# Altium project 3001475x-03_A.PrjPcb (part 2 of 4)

## Sheet 05 - JTAG, SWD, Console, UART.SchDoc: JTAG, SWD, Console, UART
size A3; PageSetup: Record=PageOptions¦CenterHorizontal=True¦CenterVertical=True¦PrintScale=0.70¦XCorrection=1.00¦YCorrection=1.00¦PrintKind=0¦BorderSize=5000000¦LeftOffset=0¦BottomOffset=0¦Orientation=2¦PaperLength=4200¦PaperWidth=2970¦Scale=100¦PaperSource=7¦PrintQuality=600¦MediaType=1¦DitherType=10¦PaperKind=A4¦PrintScaleMode=1; Author: Daniel Alesanco; SheetNumber: 5; SheetTotal: 13
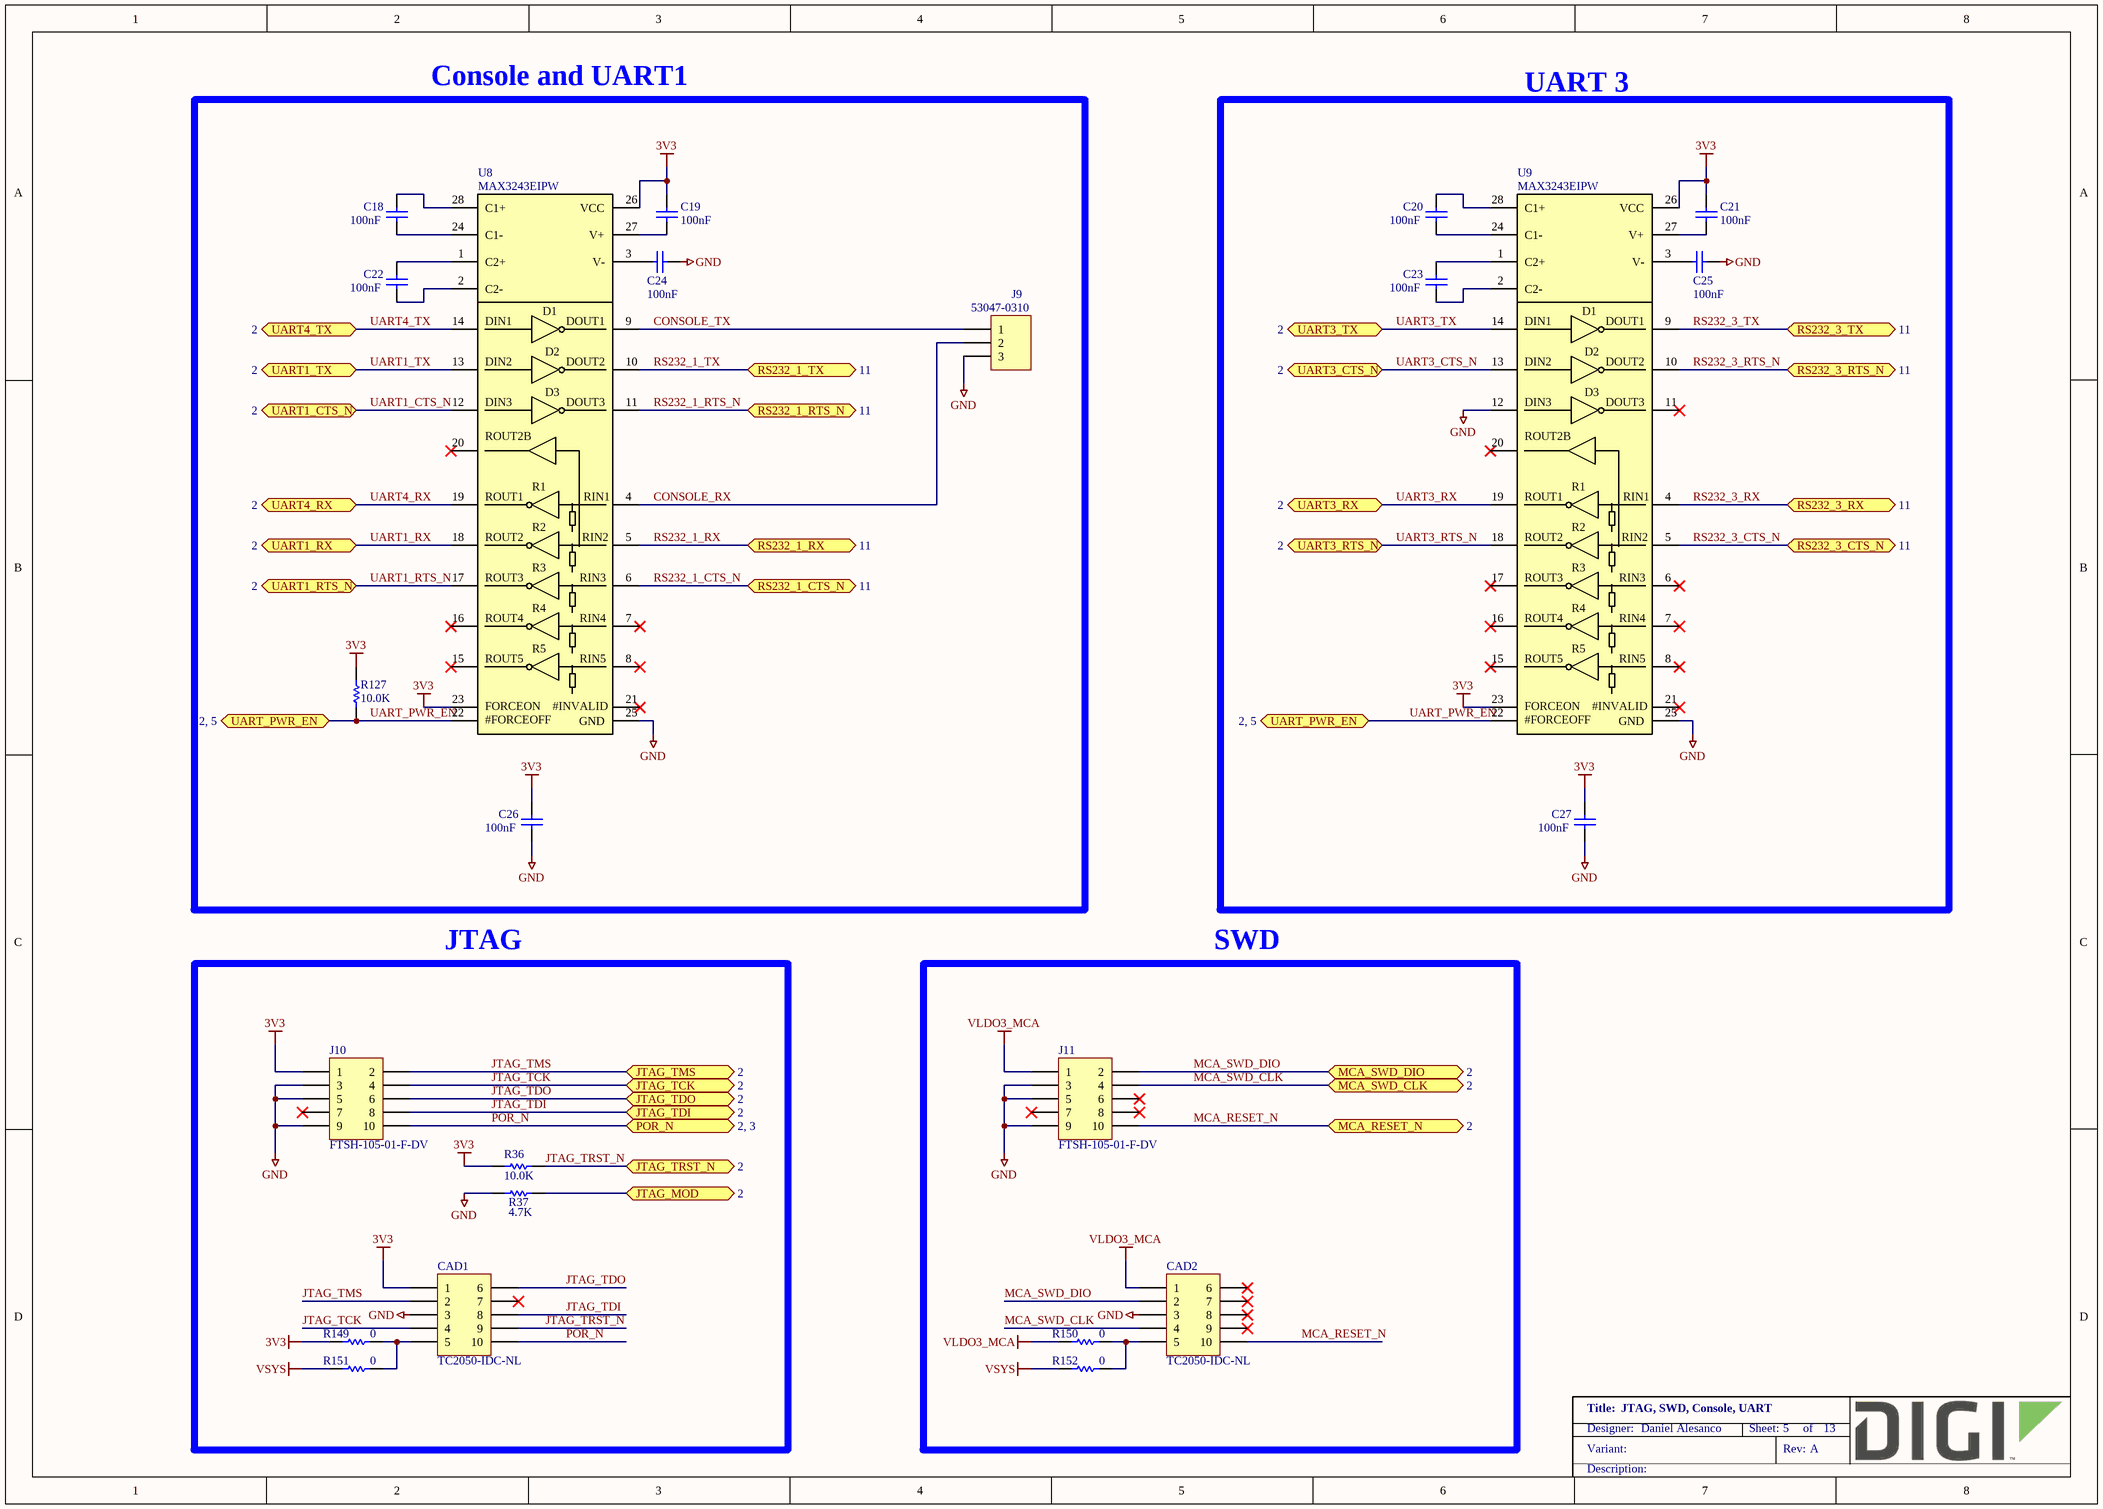
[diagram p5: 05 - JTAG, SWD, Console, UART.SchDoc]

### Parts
C18  100nF  [CAPC1005X55N]
C19  100nF  [CAPC1005X55N]
C20  100nF  [CAPC1005X55N]
C21  100nF  [CAPC1005X55N]
C22  100nF  [CAPC1005X55N]
C23  100nF  [CAPC1005X55N]
C24  100nF  [CAPC1005X55N]
C25  100nF  [CAPC1005X55N]
C26  100nF  [CAPC1005X55N]
C27  100nF  [CAPC1005X55N]
CAD1  TC2050-IDC-NL  [TC_TC2050-IDC-NL]  (no BOM)
CAD2  TC2050-IDC-NL  [TC_TC2050-IDC-NL]  (no BOM)
J9  Manufacturer_Part_Number: 53047-0310  [MOLEX_53047-0310]  (hidden comment: 1x3P)
J10  FTSH-105-01-F-DV  [SAMTEC_FTSH-105-01-F-DV]
J11  FTSH-105-01-F-DV  [SAMTEC_FTSH-105-01-F-DV]
R36  10.0K  [RESC1005X40N]
R37  4.7K  [RESC1005X40N]
R127  10.0K  [RESC1005X40N]
R149  0  [RESC1005X40N]
R150  0  [RESC1005X40N]
R151  0  [RESC1005X40N]
R152  0  [RESC1005X40N]
U8  MAX3243EIPW  [SOP65P640X120-28N]
U9  MAX3243EIPW  [SOP65P640X120-28N]

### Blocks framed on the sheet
Console and UART1: C18 C19 C22 C24 C26 J9 R127 U8
UART 3: C20 C21 C23 C25 C27 U9
JTAG: CAD1 J10 R36 R37 R149 R151
SWD: CAD2 J11 R150 R152

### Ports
JTAG_MOD (bidir, see 2), JTAG_TCK (bidir, see 2), JTAG_TDI (bidir, see 2), JTAG_TDO (bidir, see 2), JTAG_TMS (bidir, see 2), JTAG_TRST_N (bidir, see 2), MCA_RESET_N (bidir, see 2), MCA_SWD_CLK (bidir, see 2), MCA_SWD_DIO (bidir, see 2), POR_N (bidir, see 2, 3), RS232_1_CTS_N (bidir, see 11), RS232_1_RTS_N (bidir, see 11), RS232_1_RX (bidir, see 11), RS232_1_TX (bidir, see 11), RS232_3_CTS_N (bidir, see 11), RS232_3_RTS_N (bidir, see 11), RS232_3_RX (bidir, see 11), RS232_3_TX (bidir, see 11), UART1_CTS_N (bidir, see 2), UART1_RTS_N (bidir, see 2), UART1_RX (bidir, see 2), UART1_TX (bidir, see 2), UART3_CTS_N (bidir, see 2), UART3_RTS_N (bidir, see 2), UART3_RX (bidir, see 2), UART3_TX (bidir, see 2), UART4_RX (bidir, see 2), UART4_TX (bidir, see 2), UART_PWR_EN (bidir, see 2, 5)

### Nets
3V3: C19.2 C21.2 C26.2 C27.2 CAD1.1 J10.1 R36.2 R127.1 R149.1 U8.23(FORCEON) U8.26(VCC) U9.23(FORCEON) U9.26(VCC)
GND: C24.1 C25.1 C26.1 C27.1 CAD1.3 CAD2.3 J9.3 J10.3 J10.5 J10.9 J11.3 J11.5 J11.9 R37.1 U8.25(GND) U9.12(DIN3) U9.25(GND)
VLDO3_MCA: CAD2.1 J11.1 R150.1
VSYS: R151.1 R152.1
CONSOLE_RX: J9.2 U8.4(RIN1)
CONSOLE_TX: J9.1 U8.9(DOUT1)
JTAG_MOD: R37.2 ; port JTAG_MOD
JTAG_TCK: CAD1.4 J10.4 ; port JTAG_TCK
JTAG_TDI: CAD1.8 J10.8 ; port JTAG_TDI
JTAG_TDO: CAD1.6 J10.6 ; port JTAG_TDO
JTAG_TMS: CAD1.2 J10.2 ; port JTAG_TMS
JTAG_TRST_N: CAD1.9 R36.1 ; port JTAG_TRST_N
MCA_RESET_N: CAD2.10 J11.10 ; port MCA_RESET_N
MCA_SWD_CLK: CAD2.4 J11.4 ; port MCA_SWD_CLK
MCA_SWD_DIO: CAD2.2 J11.2 ; port MCA_SWD_DIO
POR_N: CAD1.10 J10.10 ; port POR_N
RS232_1_CTS_N: U8.6(RIN3) ; port RS232_1_CTS_N
RS232_1_RTS_N: U8.11(DOUT3) ; port RS232_1_RTS_N
RS232_1_RX: U8.5(RIN2) ; port RS232_1_RX
RS232_1_TX: U8.10(DOUT2) ; port RS232_1_TX
RS232_3_CTS_N: U9.5(RIN2) ; port RS232_3_CTS_N
RS232_3_RTS_N: U9.10(DOUT2) ; port RS232_3_RTS_N
RS232_3_RX: U9.4(RIN1) ; port RS232_3_RX
RS232_3_TX: U9.9(DOUT1) ; port RS232_3_TX
UART1_CTS_N: U8.12(DIN3) ; port UART1_CTS_N
UART1_RTS_N: U8.17(ROUT3) ; port UART1_RTS_N
UART1_RX: U8.18(ROUT2) ; port UART1_RX
UART1_TX: U8.13(DIN2) ; port UART1_TX
UART3_CTS_N: U9.13(DIN2) ; port UART3_CTS_N
UART3_RTS_N: U9.18(ROUT2) ; port UART3_RTS_N
UART3_RX: U9.19(ROUT1) ; port UART3_RX
UART3_TX: U9.14(DIN1) ; port UART3_TX
UART4_RX: U8.19(ROUT1) ; port UART4_RX
UART4_TX: U8.14(DIN1) ; port UART4_TX
UART_PWR_EN: R127.2 U8.22(#FORCEOFF) U9.22(#FORCEOFF) ; port UART_PWR_EN
NetC18_1: C18.1 U8.24(C1-)
NetC18_2: C18.2 U8.28(C1+)
NetC19_1: C19.1 U8.27(V+)
NetC20_1: C20.1 U9.24(C1-)
NetC20_2: C20.2 U9.28(C1+)
NetC21_1: C21.1 U9.27(V+)
NetC22_1: C22.1 U8.2(C2-)
NetC22_2: C22.2 U8.1(C2+)
NetC23_1: C23.1 U9.2(C2-)
NetC23_2: C23.2 U9.1(C2+)
NetC24_2: C24.2 U8.3(V-)
NetC25_2: C25.2 U9.3(V-)
NetCAD1_5: CAD1.5 R149.2 R151.2
NetCAD2_5: CAD2.5 R150.2 R152.2

Not connected (* = marked no-connect by the designer): CAD1 7*; CAD2 6* 7* 8* 9*; J10 7*; J11 6* 7* 8*; U8 7(RI4N)* 8(RIN5)* 15(ROUT5)* 16(ROUT4)* 20(#R2OUT)* 21(#INVALID)*; U9 6(RIN3)* 7(RI4N)* 8(RIN5)* 11(DOUT3)* 15(ROUT5)* 16(ROUT4)* 17(ROUT3)* 20(#R2OUT)* 21(#INVALID)*

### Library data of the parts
C18-C27 = 1000006: CAP 100nF 16V 10% X7R 0402; Part_Type: Capacitor; Manufacturer: Murata; Manufacturer_Part_Number: GRM155R71C104KA88D; Component_Life_Cycle_State: CAD Reviewed; Area: 0.95; Project: KITT; Tolerance: 10; Digi_PN: 14050552
CAD1 CAD2 = CAD0066: CBL PLUG-OF-NAILS 10-PIN; Part_Type: Test Point; Component_Life_Cycle_State: Created; Area: 8; Project: CCWMX6_SBC board
J9 = 1001183: CONN HEADER 3POS 1.25MM VERT TIN; Part_Type: Connector; Manufacturer: Molex; Digi_PN: 18050349; Component_Life_Cycle_State: Reviewed; Area: 17.6; Project: CCWMX6_SBC board
J10 J11 = 1000034: CONN HEADER 10POS DUAL .05" SMD; Part_Type: Connector; Manufacturer: Samtec; Note: 18000715 = Digi No. for GE WDNU; Digi_PN: 18000539; Component_Life_Cycle_State: Proven; Area: 43.55; Project: Adjustable Foundation
R36 R127 = 1000537: RES 10.0K OHM 1/10W 1% 0402 SMD; Part_Type: Resistor; Manufacturer: Panasonic - ECG; Manufacturer_Part_Number: ERJ-2RKF1002X; Component_Life_Cycle_State: CAD Reviewed; Area: 0.95; Project: KITT; Power_WV_SRF: 100; Digi_PN: 13051084
R37 = 1000038: RES 4.7K OHM 1/10W 5% 0402 SMD; Part_Type: Resistor; Manufacturer: Panasonic - ECG; Manufacturer_Part_Number: ERJ-2GEJ472X; Component_Life_Cycle_State: Proven; Area: 0.95; Project: Adjustable Foundation; Power_WV_SRF: 100; Tolerance: 5; Digi_PN: 13050549
R149-R152 = 1000076: RES 0.0 OHM 1/10W 0402 SMD; Part_Type: Resistor; Manufacturer: Panasonic - ECG; Manufacturer_Part_Number: ERJ-2GE0R00X; Component_Life_Cycle_State: Proven; Area: 0.95; Project: Adjustable Foundation; Power_WV_SRF: 10; Digi_PN: 13050387
U8 U9 = 1001499: IC RS232 3V-5.5V DRVR 28-TSSOP; Manufacturer: Texas Instruments; Digi_PN: 16050972; Component_Life_Cycle_State: Reviewed; Area: 67; Project: CCWMX6_SBC board

## Sheet 06 - Gigabit Ethernet.SchDoc: Gigabit Ethernet
size A3; PageSetup: Record=PageOptions¦CenterHorizontal=True¦CenterVertical=True¦PrintScale=0.70¦XCorrection=1.00¦YCorrection=1.00¦PrintKind=0¦BorderSize=5000000¦LeftOffset=0¦BottomOffset=0¦Orientation=2¦PaperLength=4200¦PaperWidth=2970¦Scale=100¦PaperSource=7¦PrintQuality=600¦MediaType=1¦DitherType=10¦PaperKind=A4¦PrintScaleMode=1; Author: Daniel Alesanco; SheetNumber: 6; SheetTotal: 13
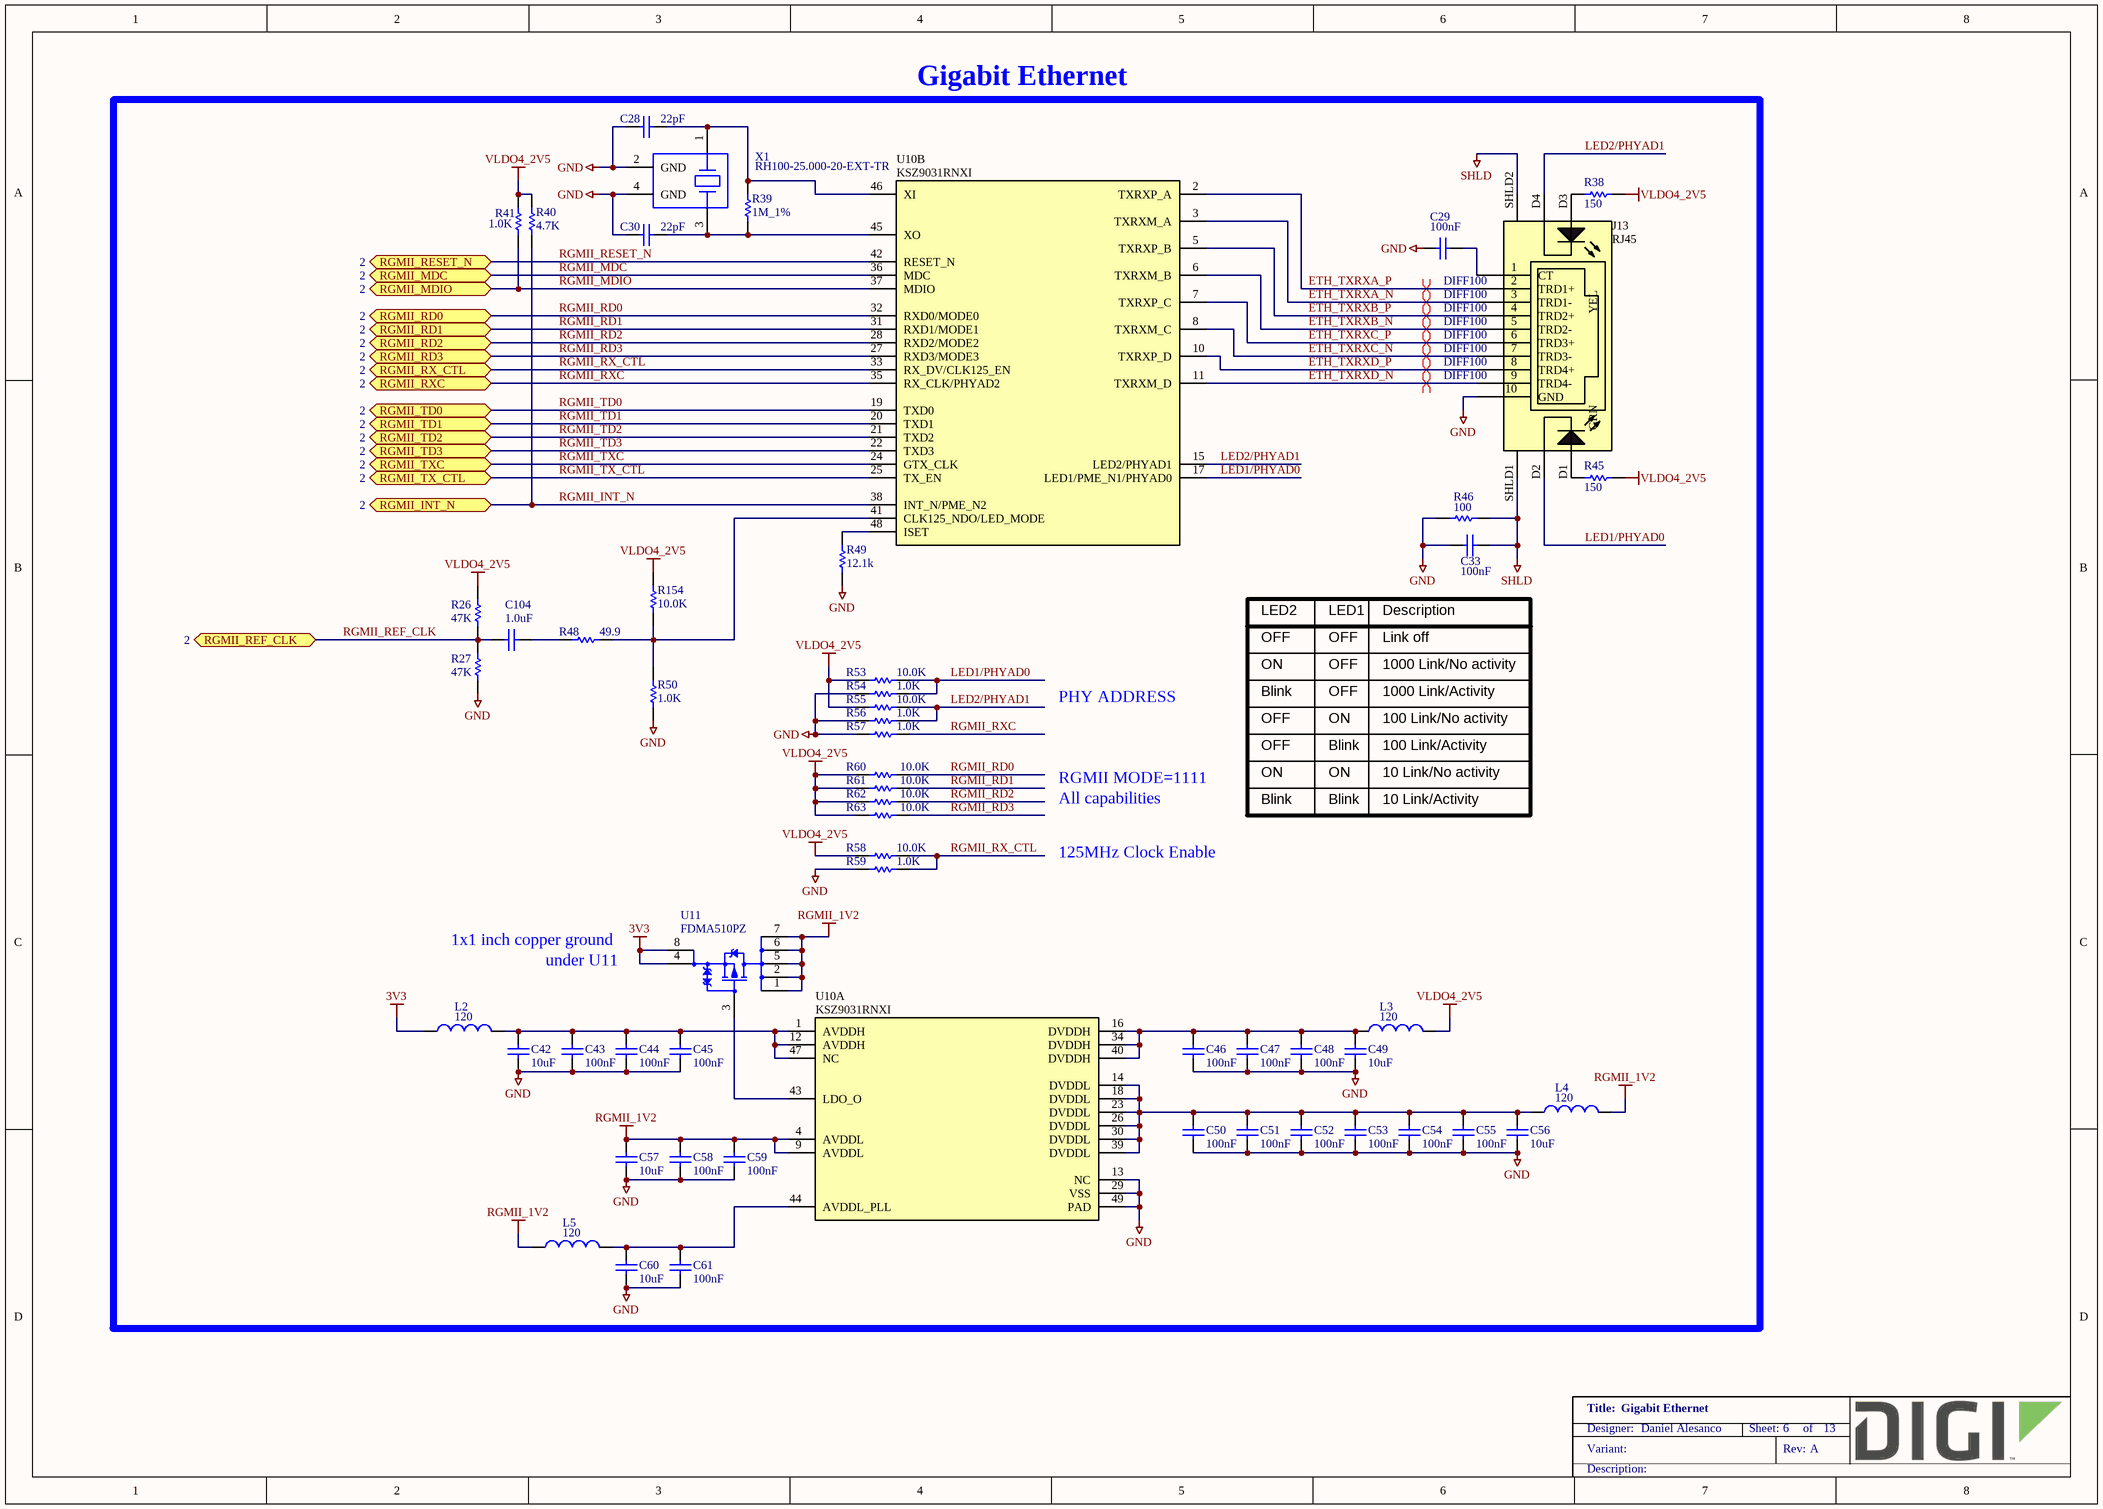
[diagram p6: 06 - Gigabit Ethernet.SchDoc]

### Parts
C28  22pF  [CAPC1005X55N]
C29  100nF  [CAPC1005X55N]
C30  22pF  [CAPC1005X55N]
C33  100nF  [CAPC1005X55N]
C42  10uF  [CAPC1005X55N]
C43  100nF  [CAPC1005X55N]
C44  100nF  [CAPC1005X55N]
C45  100nF  [CAPC1005X55N]
C46  100nF  [CAPC1005X55N]
C47  100nF  [CAPC1005X55N]
C48  100nF  [CAPC1005X55N]
C49  10uF  [CAPC1005X55N]
C50  100nF  [CAPC1005X55N]
C51  100nF  [CAPC1005X55N]
C52  100nF  [CAPC1005X55N]
C53  100nF  [CAPC1005X55N]
C54  100nF  [CAPC1005X55N]
C55  100nF  [CAPC1005X55N]
C56  10uF  [CAPC1005X55N]
C57  10uF  [CAPC1005X55N]
C58  100nF  [CAPC1005X55N]
C59  100nF  [CAPC1005X55N]
C60  10uF  [CAPC1005X55N]
C61  100nF  [CAPC1005X55N]
C104  1.0uF  [CAPC1005X55N]
J13  RJ45  [BELFUSE_61001-F]
L2  120  [INDC1005X60N]
L3  120  [INDC1005X60N]
L4  120  [INDC1005X60N]
L5  120  [INDC1005X60N]
R26  47K  [RESC1005X40N]
R27  47K  [RESC1005X40N]
R38  150  [RESC1005X40N]
R39  1M_1%  [RESC1005X40N]
R40  4.7K  [RESC1005X40N]
R41  1.0K  [RESC1005X40N]
R45  150  [RESC1005X40N]
R46  100  [RESC1005X40N]
R48  49.9  [RESC1005X40N]
R49  12.1k  [RESC1005X40N]
R50  1.0K  [RESC1005X40N]
R53  10.0K  [RESC1005X40N]
R54  1.0K  [RESC1005X40N]
R55  10.0K  [RESC1005X40N]
R56  1.0K  [RESC1005X40N]
R57  1.0K  [RESC1005X40N]
R58  10.0K  [RESC1005X40N]
R59  1.0K  [RESC1005X40N]
R60  10.0K  [RESC1005X40N]
R61  10.0K  [RESC1005X40N]
R62  10.0K  [RESC1005X40N]
R63  10.0K  [RESC1005X40N]
R154  10.0K  [RESC1005X40N]
U10  KSZ9031RNXI  [QFN50P700X700X100-49N]  (parts A,B of 2)
U11  FDMA510PZ  [DFN200X200X80-6N]
X1  RH100-25.000-20-EXT-TR  [OSC210P320X250X90-4N]

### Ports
RGMII_INT_N (bidir, see 2), RGMII_MDC (bidir, see 2), RGMII_MDIO (bidir, see 2), RGMII_RD0 (bidir, see 2), RGMII_RD1 (bidir, see 2), RGMII_RD2 (bidir, see 2), RGMII_RD3 (bidir, see 2), RGMII_REF_CLK (bidir, see 2), RGMII_RESET_N (bidir, see 2), RGMII_RX_CTL (bidir, see 2), RGMII_RXC (bidir, see 2), RGMII_TD0 (bidir, see 2), RGMII_TD1 (bidir, see 2), RGMII_TD2 (bidir, see 2), RGMII_TD3 (bidir, see 2), RGMII_TX_CTL (bidir, see 2), RGMII_TXC (bidir, see 2)

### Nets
3V3: L2.1 U11.4(S) U11.8(S)
GND: C28.1 C29.1 C30.1 C33.2 C42.1 C43.1 C44.1 C45.1 C46.1 C47.1 C48.1 C49.1 C50.1 C51.1 C52.1 C53.1 C54.1 C55.1 C56.1 C57.1 C58.1 C59.1 C60.1 C61.1 J13.10(GND) R27.1 R46.1 R49.1 R50.1 R54.2 R56.2 R57.2 R59.2 U10.13(NC) U10.29(VSS) U10.49(PAD) X1.2(GND) X1.4(GND)
RGMII_1V2: C57.2 C58.2 C59.2 L4.2 L5.1 U10.4(AVDDL) U10.9(AVDDL) U11.1(D) U11.2(D) U11.5(D) U11.6(D) U11.7(D)
SHLD: C33.1 J13.SHLD1(SHLD) J13.SHLD2(SHLD) R46.2
VLDO4_2V5: L3.2 R26.2 R38.2 R40.2 R41.2 R45.2 R53.2 R55.2 R58.2 R60.2 R61.2 R62.2 R63.2 R154.1
ETH_TXRXA_N: J13.3(TRD1-) U10.3(TXRXM_A)
ETH_TXRXA_P: J13.2(TRD1+) U10.2(TXRXP_A)
ETH_TXRXB_N: J13.5(TRD2-) U10.6(TXRXM_B)
ETH_TXRXB_P: J13.4(TRD2+) U10.5(TXRXP_B)
ETH_TXRXC_N: J13.7(TRD3-) U10.8(TXRXM_C)
ETH_TXRXC_P: J13.6(TRD3+) U10.7(TXRXP_C)
ETH_TXRXD_N: J13.9(TRD4-) U10.11(TXRXM_D)
ETH_TXRXD_P: J13.8(TRD4+) U10.10(TXRXP_D)
LED1/PHYAD0: J13.D2 R53.1 R54.1 U10.17(LED1/PME_N1/PHYAD0)
LED2/PHYAD1: J13.D4 R55.1 R56.1 U10.15(LED2/PHYAD1)
RGMII_INT_N: R40.1 U10.38(INT_N/PME_N2) ; port RGMII_INT_N
RGMII_MDC: U10.36(MDC) ; port RGMII_MDC
RGMII_MDIO: R41.1 U10.37(MDIO) ; port RGMII_MDIO
RGMII_RD0: R60.1 U10.32(RXD0/MODE0) ; port RGMII_RD0
RGMII_RD1: R61.1 U10.31(RXD1/MODE1) ; port RGMII_RD1
RGMII_RD2: R62.1 U10.28(RXD2/MODE2) ; port RGMII_RD2
RGMII_RD3: R63.1 U10.27(RXD3/MODE3) ; port RGMII_RD3
RGMII_REF_CLK: C104.1 R26.1 R27.2 ; port RGMII_REF_CLK
RGMII_RESET_N: U10.42(RESET_N) ; port RGMII_RESET_N
RGMII_RX_CTL: R58.1 R59.1 U10.33(RX_DV/CLK125_EN) ; port RGMII_RX_CTL
RGMII_RXC: R57.1 U10.35(RX_CLK/PHYAD2) ; port RGMII_RXC
RGMII_TD0: U10.19(TXD0) ; port RGMII_TD0
RGMII_TD1: U10.20(TXD1) ; port RGMII_TD1
RGMII_TD2: U10.21(TXD2) ; port RGMII_TD2
RGMII_TD3: U10.22(TXD3) ; port RGMII_TD3
RGMII_TX_CTL: U10.25(TX_EN) ; port RGMII_TX_CTL
RGMII_TXC: U10.24(GTX_CLK) ; port RGMII_TXC
NetC28_2: C28.2 R39.2 U10.46(XI) X1.1
NetC29_2: C29.2 J13.1(CT)
NetC30_2: C30.2 R39.1 U10.45(XO) X1.3
NetC42_2: C42.2 C43.2 C44.2 C45.2 L2.2 U10.1(AVDDH) U10.12(AVDDH) U10.47(NC)
NetC46_2: C46.2 C47.2 C48.2 C49.2 L3.1 U10.16(DVDDH) U10.34(DVDDH) U10.40(DVDDH)
NetC50_2: C50.2 C51.2 C52.2 C53.2 C54.2 C55.2 C56.2 L4.1 U10.14(DVDDL) U10.18(DVDDL) U10.23(DVDDL) U10.26(DVDDL) U10.30(DVDDL) U10.39(DVDDL)
NetC60_2: C60.2 C61.2 L5.2 U10.44(AVDDL_PLL)
NetC104_2: C104.2 R48.1
NetJ13_D1: J13.D1 R45.1
NetJ13_D3: J13.D3 R38.1
NetR48_2: R48.2 R50.2 R154.2 U10.41(CLK125_NDO/LED_MODE)
NetR49_2: R49.2 U10.48(ISET)
NetU10_43: U10.43(LDO_O) U11.3(G)

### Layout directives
differential pair; net class DIFF100: ETH_TXRXA_N, ETH_TXRXA_P, ETH_TXRXB_N, ETH_TXRXB_P, ETH_TXRXC_N, ETH_TXRXC_P, ETH_TXRXD_N, ETH_TXRXD_P

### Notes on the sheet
- Gigabit Ethernet
- LED2
- OFF
- LED1
- Description
- Link off
- PHY ADDRESS
- ON
- Blink
- 1000 Link/No activity
- 1000 Link/Activity
- 100 Link/No activity
- RGMII MODE=1111
- 100 Link/Activity
- 10 Link/No activity
- All capabilities
- 125MHz Clock Enable
- 10 Link/Activity
- 1x1 inch copper ground
- under U11

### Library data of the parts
C28 C30 = 1001166: CAP CER 22PF 50V 5% NP0 0402; Part_Type: Capacitor; Manufacturer: Murata; Manufacturer_Part_Number: GRM1555C1H220JA01D; Digi_PN: 14050367; Component_Life_Cycle_State: Reviewed; Area: 0.95; Project: CCWMX6_SBC board; Temp_Coef: C0G, NP0; Note: 14050749 = Digi No. for GE WDNU
C29 C33 C43-C48 C50-C55 C58 C59 C61 = 1000006: as C18-C27 on sheet 05 - JTAG, SWD, Console, UART
C42 C49 C56 C57 C60 = 1001168: CAP CER 10UF 10V 20% X5R 0402; Part_Type: Capacitor; Manufacturer: Samsung; Manufacturer_Part_Number: CL05A106MP5NUNC; Digi_PN: 14050689; Component_Life_Cycle_State: Reviewed; Area: 0.95; Project: CCWMX6_SBC board
C104 = 1001167: CAP CER 1UF 10V 10% X5R 0402; Part_Type: Capacitor; Manufacturer: Murata; Manufacturer_Part_Number: GRM155R61A105KE15D; Digi_PN: 14050399; Component_Life_Cycle_State: Reviewed; Area: 0.95; Project: CCWMX6_SBC board
J13 = 1001966: CONN MAGJACK 1PORT 1000 BASE-T, -40/85°C; Part_Type: Connector; Manufacturer: XMultiple; Manufacturer_Part_Number: XMG-1108D1006-1; Digi_PN: 18000732; Component_Life_Cycle_State: Created; Area: 348,2467; Project: CCWMX6_SBC board
L2-L5 = 1001175: FERRITE BEAD 120 OHM .35A 0402; Part_Type: Filter; Manufacturer: Wurth Electronics Inc; Manufacturer_Part_Number: 7427927112; Digi_PN: 21000128; Component_Life_Cycle_State: Reviewed; Area: 1.12; Project: CCWMX6_SBC board
R26 R27 = 1001155: RES 47.0K OHM 1/16W 1% 0402 SMD; Part_Type: Resistor; Manufacturer: Vishay Dale; Manufacturer_Part_Number: CRCW040247K0FKED; Digi_PN: 13050646; Component_Life_Cycle_State: Reviewed; Area: 0.95; Project: CCWMX6_SBC board
R38 R45 = 1000465: RES 150 OHM 1/10W 1% 0402 SMD; Part_Type: Resistor; Manufacturer: Panasonic - ECG; Manufacturer_Part_Number: ERJ-2RKF1500X; Digi_PN: 13050557; Component_Life_Cycle_State: CAD Reviewed; Area: 0.95; Project: KITT; Power_WV_SRF: 100
R39 = 1000971: RES 1.00M OHM 1/16W 1% 0402 SMD; Part_Type: Resistor; Manufacturer: Yageo; Manufacturer_Part_Number: RC0402FR-071ML; Digi_PN: 13050561; Component_Life_Cycle_State: Reviewed; Area: 0.95; Project: ConnectCore i.MX6 module; Power_WV_SRF: 63; Tolerance: 1; Note: 13051098 = Digi No. for GE WDNU
R40 = 1000038: as R37 on sheet 05 - JTAG, SWD, Console, UART
R41 R50 R54 R56 R57 R59 = 1000079: RES 1.00K OHM 1/10W 1% 0402 SMD; Part_Type: Resistor; Manufacturer: Panasonic - ECG; Manufacturer_Part_Number: ERJ-2RKF1001X; Digi_PN: 13051085; Component_Life_Cycle_State: Proven; Area: 0.95; Project: Adjustable Foundation; Power_WV_SRF: 10
R46 = 1000467: RES 100 OHM 1/10W 1% 0402 SMD; Part_Type: Resistor; Manufacturer: Panasonic - ECG; Manufacturer_Part_Number: ERJ-2RKF1000X; Component_Life_Cycle_State: CAD Reviewed; Area: 0.95; Project: KITT; Digi_PN: 13051087
R48 = 1000466: RES 49.9 OHM 1/10W 1% 0402 SMD; Part_Type: Resistor; Manufacturer: Panasonic - ECG; Manufacturer_Part_Number: ERJ-2RKF49R9X; Component_Life_Cycle_State: CAD Reviewed; Area: 0.95; Project: KITT; Power_WV_SRF: 100; Digi_PN: 13051083
R49 = 1000828: RES 12.1K OHM 1/10W 1% 0402 SMD; Part_Type: Resistor; Manufacturer: Panasonic - ECG; Manufacturer_Part_Number: ERJ-2RKF1212X; Component_Life_Cycle_State: Reviewed; Area: 0.95; Project: SmartMeter2; Power_WV_SRF: 100; Digi_PN: 13051088
R53 R55 R58 R60-R63 R154 = 1000537: as R36 on sheet 05 - JTAG, SWD, Console, UART
U10 = 1001110: IC TXRX ETHERNET 48-QFN; Manufacturer: Micrel; Digi_PN: 16051862; Component_Life_Cycle_State: Reviewed; Area: 49; Project: CCWMX6_SBC board
U11 = 1001205: MOSFET P-CH 20V 7.8A 6-MICROFET; Part_Type: IC; Manufacturer: Fairchild Semiconductor; Digi_PN: 17050636; Component_Life_Cycle_State: Reviewed; Area: 4; Project: CCWMX6_SBC board
X1 = 1001497: SMCRY,25MHZ 50PPM 20PF RH100 EXT; Part_Type: Crystals-Oscillators; Manufacturer: Raltron; Digi_PN: 20000285; Component_Life_Cycle_State: Reviewed; Area: 3.2; Project: CCWMX6_SBC board

## Sheet 07 - USB OTG, USB HUB, USB Host.SchDoc: USB OTG, USB Hub, USB Host
size A3; PageSetup: Record=PageOptions¦CenterHorizontal=True¦CenterVertical=True¦PrintScale=0.70¦XCorrection=1.00¦YCorrection=1.00¦PrintKind=0¦BorderSize=5000000¦LeftOffset=0¦BottomOffset=0¦Orientation=2¦PaperLength=4200¦PaperWidth=2970¦Scale=100¦PaperSource=7¦PrintQuality=600¦MediaType=1¦DitherType=10¦PaperKind=A4¦PrintScaleMode=1; Author: Daniel Alesanco; SheetNumber: 7; SheetTotal: 13
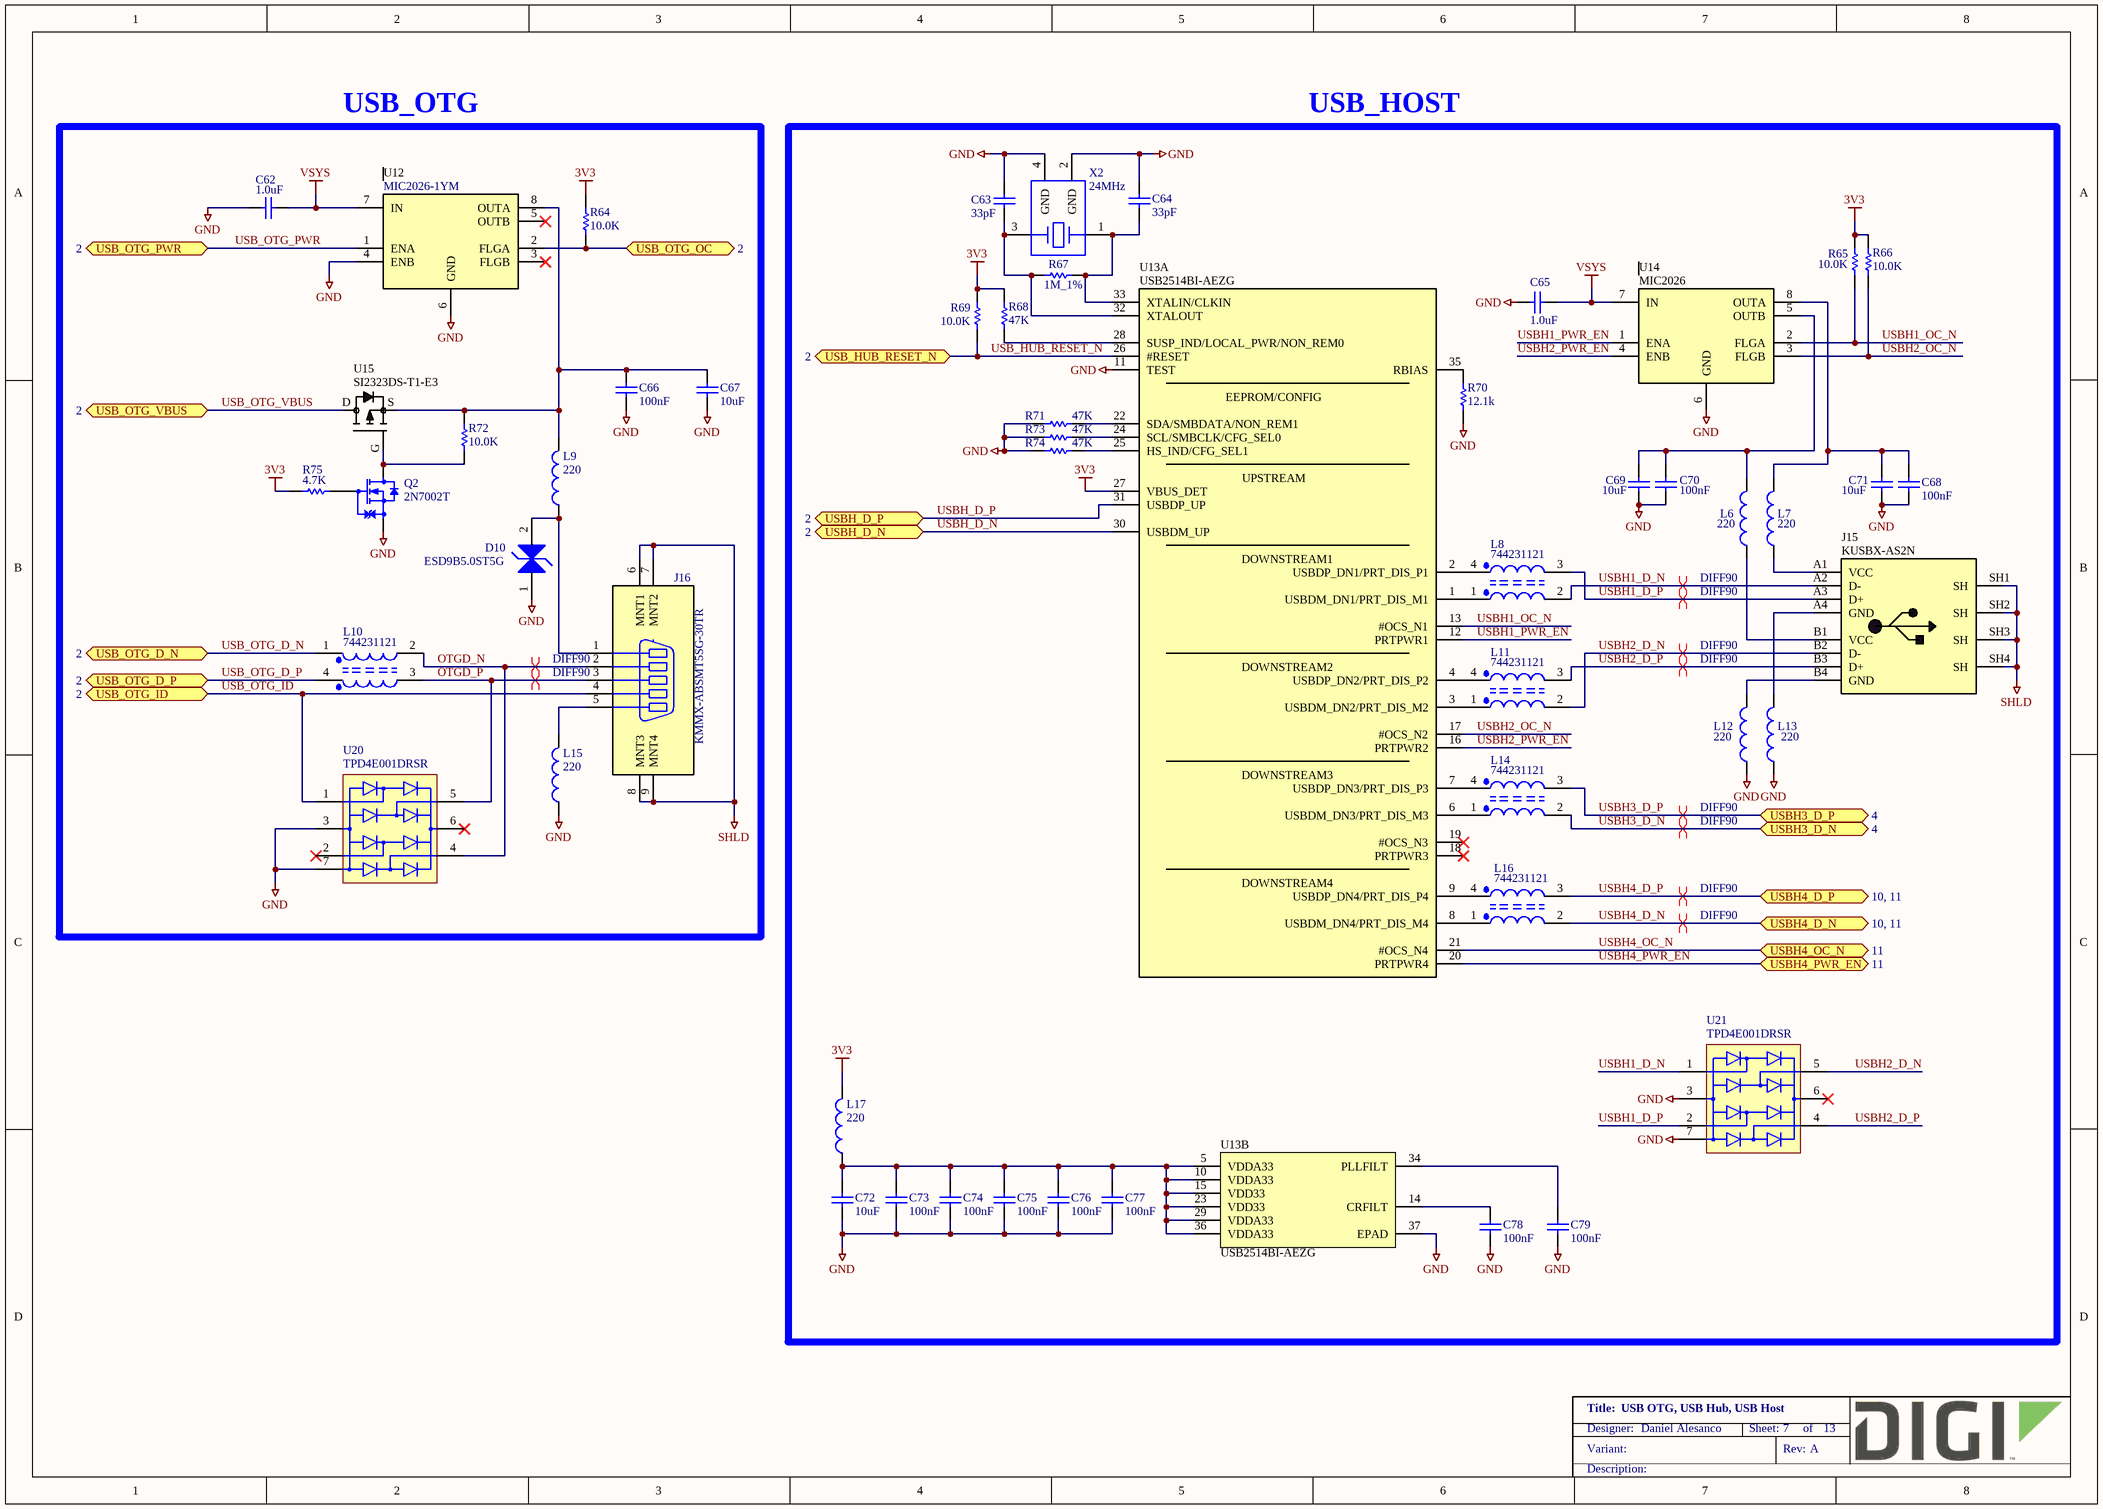
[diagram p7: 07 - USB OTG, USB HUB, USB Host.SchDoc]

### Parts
C62  1.0uF  [CAPC1005X55N]
C63  33pF  [CAPC1005X55N]
C64  33pF  [CAPC1005X55N]
C65  1.0uF  [CAPC1005X55N]
C66  100nF  [CAPC1005X55N]
C67  10uF  [CAPC1005X55N]
C68  100nF  [CAPC1005X55N]
C69  10uF  [CAPC1005X55N]
C70  100nF  [CAPC1005X55N]
C71  10uF  [CAPC1005X55N]
C72  10uF  [CAPC1005X55N]
C73  100nF  [CAPC1005X55N]
C74  100nF  [CAPC1005X55N]
C75  100nF  [CAPC1005X55N]
C76  100nF  [CAPC1005X55N]
C77  100nF  [CAPC1005X55N]
C78  100nF  [CAPC1005X55N]
C79  100nF  [CAPC1005X55N]
D10  ESD9B5.0ST5G  [SODFL1006X43N12]
J15  KUSBX-AS2N  [KYCON_KUSBX-AS2N]
J16  KMMX-ABSMT5SG-30TR  [KYCON_KMMX-ABSMT5]
L6  220  [INDC2013X110N]
L7  220  [INDC2013X110N]
L8  744231121  [FIL_DLW21H]
L9  220  [INDC2013X110N]
L10  744231121  [FIL_DLW21H]
L11  744231121  [FIL_DLW21H]
L12  220  [INDC2013X110N]
L13  220  [INDC2013X110N]
L14  744231121  [FIL_DLW21H]
L15  220  [INDC2013X110N]
L16  744231121  [FIL_DLW21H]
L17  220  [INDC2013X110N]
Q2  2N7002T  [SOTFL50P160X80_GSD-3N]
R64  10.0K  [RESC1005X40N]
R65  10.0K  [RESC1005X40N]
R66  10.0K  [RESC1005X40N]
R67  1M_1%  [RESC1005X40N]
R68  47K  [RESC1005X40N]
R69  10.0K  [RESC1005X40N]
R70  12.1k  [RESC1005X40N]
R71  47K  [RESC1005X40N]
R72  10.0K  [RESC1005X40N]
R73  47K  [RESC1005X40N]
R74  47K  [RESC1005X40N]
R75  4.7K  [RESC1005X40N]
U12  Manufacturer_Part_Number: MIC2026-1YM  [SOIC127P600X175-8N]  (hidden comment: MIC2026)
U13  USB2514BI-AEZG  [QFN50P600X600X100-37AN]  (parts A,B of 2)
U14  MIC2026  [SOIC127P600X175-8N]
U15  SI2323DS-T1-E3  [SOT95P240X110_GSD-3N]
U20  TPD4E001DRSR  [SON95P300X300X80-7N]
U21  TPD4E001DRSR  [SON95P300X300X80-7N]
X2  24MHz  [XTAL_C3E-3427]

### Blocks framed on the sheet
USB_OTG: C62 C66 C67 D10 J16 L9 L10 L15 Q2 R64 R72 R75 U12 U15 U20
USB_HOST: C63-C65 C68-C79 J15 L6-L8 L11-L14 L16 L17 R65-R71 R73 R74 U13 U14 U21 X2

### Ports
USB_HUB_RESET_N (bidir, see 2), USB_OTG_D_N (bidir, see 2), USB_OTG_D_P (bidir, see 2), USB_OTG_ID (bidir, see 2), USB_OTG_OC (bidir, see 2), USB_OTG_PWR (bidir, see 2), USB_OTG_VBUS (bidir, see 2), USBH3_D_N (bidir, see 4), USBH3_D_P (bidir, see 4), USBH4_D_N (bidir, see 10, 11), USBH4_D_P (bidir, see 10, 11), USBH4_OC_N (bidir, see 11), USBH4_PWR_EN (bidir, see 11), USBH_D_N (bidir, see 2), USBH_D_P (bidir, see 2)

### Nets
3V3: L17.2 R64.2 R65.2 R66.2 R68.2 R69.1 R75.1 U13.27(VBUS_DET)
GND: C62.1 C63.2 C64.2 C65.2 C66.1 C67.1 C68.1 C69.1 C70.1 C71.1 C72.1 C73.1 C74.1 C75.1 C76.1 C77.1 C78.1 C79.1 D10.1 L12.1 L13.1 L15.1 Q2.S R70.1 R71.1 R73.1 R74.1 U12.4(ENB) U12.6(GND) U13.11(TEST) U13.37(EPAD) U14.6(GND) U20.3(GND) U20.7(GND) U21.3(GND) U21.7(GND) X2.2(GND) X2.4(GND)
SHLD: J15.SH1(SH) J15.SH2(SH) J15.SH3(SH) J15.SH4(SH) J16.6(MNT1) J16.7(MNT2) J16.8(MNT3) J16.9(MNT4)
VSYS: C62.2 C65.1 U12.7(IN) U14.7(IN)
OTGD_N: J16.2 L10.2 U20.4(I/O)
OTGD_P: J16.3 L10.3 U20.5(I/O)
USB_HUB_RESET_N: R69.2 U13.26(#RESET) ; port USB_HUB_RESET_N
USB_OTG_D_N: L10.1 ; port USB_OTG_D_N
USB_OTG_D_P: L10.4 ; port USB_OTG_D_P
USB_OTG_ID: J16.4 U20.1(I/O) ; port USB_OTG_ID
USB_OTG_OC: R64.1 U12.2(FLGA) ; port USB_OTG_OC
USB_OTG_PWR: U12.1(ENA) ; port USB_OTG_PWR
USB_OTG_VBUS: U15.D ; port USB_OTG_VBUS
USBH1_D_N: J15.A2(D-) L8.2 U21.1(I/O)
USBH1_D_P: J15.A3(D+) L8.3 U21.2(I/O)
USBH1_OC_N: R65.1 U13.13(#OCS_N1) U14.2(FLGA)
USBH1_PWR_EN: U13.12(PRTPWR1) U14.1(ENA)
USBH2_D_N: J15.B2(D-) L11.2 U21.5(I/O)
USBH2_D_P: J15.B3(D+) L11.3 U21.4(I/O)
USBH2_OC_N: R66.1 U13.17(#OCS_N2) U14.3(FLGB)
USBH2_PWR_EN: U13.16(PRTPWR2) U14.4(ENB)
USBH3_D_N: L14.2 ; port USBH3_D_N
USBH3_D_P: L14.3 ; port USBH3_D_P
USBH4_D_N: L16.2 ; port USBH4_D_N
USBH4_D_P: L16.3 ; port USBH4_D_P
USBH4_OC_N: U13.21(#OCS_N4) ; port USBH4_OC_N
USBH4_PWR_EN: U13.20(PRTPWR4) ; port USBH4_PWR_EN
USBH_D_N: U13.30(USBDM_UP) ; port USBH_D_N
USBH_D_P: U13.31(USBDP_UP) ; port USBH_D_P
NetC63_1: C63.1 R67.1 U13.32(XTALOUT) X2.3
NetC64_1: C64.1 R67.2 U13.33(XTALIN/CLKIN) X2.1
NetC66_2: C66.2 C67.2 L9.2 R72.1 U12.8(OUTA) U15.S
NetC68_2: C68.2 C71.2 L7.2 U14.8(OUTA)
NetC69_2: C69.2 C70.2 L6.2 U14.5(OUTB)
NetC72_2: C72.2 C73.2 C74.2 C75.2 C76.2 C77.2 L17.1 U13.5(VDDA33) U13.10(VDDA33) U13.15(VDD33) U13.23(VDD33) U13.29(VDDA33) U13.36(VDDA33)
NetC78_2: C78.2 U13.14(CRFILT)
NetC79_2: C79.2 U13.34(PLLFILT)
NetD10_2: D10.2 J16.1 L9.1
NetJ15_A1: J15.A1(VCC) L7.1
NetJ15_A4: J15.A4(GND) L13.2
NetJ15_B1: J15.B1(VCC) L6.1
NetJ15_B4: J15.B4(GND) L12.2
NetJ16_5: J16.5 L15.2
NetL8_1: L8.1 U13.1(USBDM_DN1/PRT_DIS_M1)
NetL8_4: L8.4 U13.2(USBDP_DN1/PRT_DIS_P1)
NetL11_1: L11.1 U13.3(USBDM_DN2/PRT_DIS_M2)
NetL11_4: L11.4 U13.4(USBDP_DN2/PRT_DIS_P2)
NetL14_1: L14.1 U13.6(USBDM_DN3/PRT_DIS_M3)
NetL14_4: L14.4 U13.7(USBDP_DN3/PRT_DIS_P3)
NetL16_1: L16.1 U13.8(USBDM_DN4/PRT_DIS_M4)
NetL16_4: L16.4 U13.9(USBDP_DN4/PRT_DIS_P4)
NetQ2_D: Q2.D R72.2 U15.G
NetQ2_G: Q2.G R75.2
NetR68_1: R68.1 U13.28(SUSP_IND/LOCAL_PWR/NON_REM0)
NetR70_2: R70.2 U13.35(RBIAS)
NetR71_2: R71.2 U13.22(SDA/SMBDATA/NON_REM1)
NetR73_2: R73.2 U13.24(SCL/SMBCLK/CFG_SEL0)
NetR74_2: R74.2 U13.25(HS_IND/CFG_SEL1)

Not connected (* = marked no-connect by the designer): U12 3(FLGB)* 5(OUTB)*; U13 18(PRTPWR3)* 19(#OCS_N3)*; U20 2(I/O)* 6(VCC)*; U21 6(VCC)*

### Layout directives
differential pair; net class DIFF90: OTGD_N, OTGD_P, USBH1_D_N, USBH1_D_P, USBH2_D_N, USBH2_D_P, USBH3_D_N, USBH3_D_P, USBH4_D_N, USBH4_D_P

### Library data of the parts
C62 C65 = 1001167: as C104 on sheet 06 - Gigabit Ethernet
C63 C64 = 1002646: CAP CER 33PF 50V C0G/NP0 0402; Part_Type: Capacitor; Manufacturer: Murata; Manufacturer_Part_Number: GCM1555C1H330JA16D; Digi_PN: 14050400; Component_Life_Cycle_State: Reviewed; Area: 2.12; Project: SmartSense - International Certification; Voltage: 50; Tolerance: 5%
C66 C68 C70 C73-C79 = 1000006: as C18-C27 on sheet 05 - JTAG, SWD, Console, UART
C67 C69 C71 C72 = 1001168: as C42 on sheet 06 - Gigabit Ethernet
D10 = 1001264: TVS DIODE 5VWM SOD923; Part_Type: Diodes; Manufacturer: On Semiconductor; Digi_PN: 17050587; Component_Life_Cycle_State: Reviewed; Area: 1.5; Project: CCWMX6_SBC board
J15 = 1001121: USB Stacked Dual A type; Part_Type: Connector; Manufacturer: KYCON; Digi_PN: 18000276; Component_Life_Cycle_State: Reviewed; Area: 164; Project: CCWMX6_SBC board
J16 = 1001117: CONN RECEPT MICRO-USB TYPE AB R/A; Part_Type: Connector; Manufacturer: KYCON; Digi_PN: 18000401; Component_Life_Cycle_State: Reviewed; Area: 40; Project: CCWMX6_SBC board
L6 L7 L9 L12 L13 L15 L17 = 1001174: FERRITE BEAD 220 OHM 2.0A 0805; Manufacturer: Wurth Electronics Inc; Manufacturer_Part_Number: 742792022; Digi_PN: 21000146; Component_Life_Cycle_State: Reviewed; Area: 4.24; Project: CCWMX6_SBC board
L8 L10 L11 L14 L16 = 1001173: CHOKE COM MODE 120 OHM .37A; Part_Type: Inductor; Manufacturer: Wurth Electronics Inc; Digi_PN: 21000143; Component_Life_Cycle_State: Reviewed; Area: 2.4; Project: CCWMX6_SBC board
Q2 = 1000715: MOSFET N-CH 60V 115MA SOT-523F; Part_Type: Transistor; Manufacturer: Fairchild Semiconductor; Digi_PN: 17050797; Component_Life_Cycle_State: CAD Reviewed; Area: 3.06; Project: SmartMeter2; Note: 17050841 = Digi No. for GE WDNU
R64-R66 R69 R72 = 1000537: as R36 on sheet 05 - JTAG, SWD, Console, UART
R67 = 1000971: as R39 on sheet 06 - Gigabit Ethernet
R68 R71 R73 R74 = 1001155: as R26 on sheet 06 - Gigabit Ethernet
R70 = 1000828: as R49 on sheet 06 - Gigabit Ethernet
R75 = 1000038: as R37 on sheet 05 - JTAG, SWD, Console, UART
U12 = 1001143: IC SW DISTRIBUTION 2CHAN 8SOIC; Manufacturer: Micrel; Digi_PN: 16051879; Component_Life_Cycle_State: Reviewed; Area: 29.58; Project: CCWMX6_SBC board
U13 = 1001114: 4-PORT USB 2.0 HUB CTRLR 36VQFN; Part_Type: IC; Manufacturer: SMSC; Digi_PN: 16051280; Component_Life_Cycle_State: Reviewed; Area: 36; Project: CCWMX6_SBC board
U14 = 1001143: IC SW DISTRIBUTION 2CHAN 8SOIC; Manufacturer: Micrel; Manufacturer_Part_Number: MIC2026-1YM; Digi_PN: 16051879; Component_Life_Cycle_State: Reviewed; Area: 29.58; Project: CCWMX6_SBC board
U15 = 1001163: MOSFET P-CH 20V 3.7A SOT23-3; Part_Type: IC; Manufacturer: Vishay Siliconix; Digi_PN: 17050358; Component_Life_Cycle_State: Reviewed; Area: 10.92; Project: CCWMX6_SBC board
U20 U21 = 1001265: TVS DIODE 5.5VWM 6SON; Part_Type: IC; Manufacturer: Texas Instruments; Digi_PN: 17050690; Component_Life_Cycle_State: Reviewed; Area: 10; Project: CCWMX6_SBC board; Note: 17050839 = Digi No. for GE WDNU
X2 = 1001134: CRYSTAL 24MHZ 18PF SMD; Part_Type: Crystals-Oscillators; Manufacturer: Aker; Manufacturer_Part_Number: C3E-24.000-18-3030-X-R; Digi_PN: 20000223; Component_Life_Cycle_State: Reviewed; Area: 9.18; Project: CCWMX6_SBC board

## Sheet 08 - Displays, HDMI, Cameras.SchDoc: Displays, HDMI and Cameras
size A3; PageSetup: Record=PageOptions¦CenterHorizontal=True¦CenterVertical=True¦PrintScale=0.70¦XCorrection=1.00¦YCorrection=1.00¦PrintKind=0¦BorderSize=5000000¦LeftOffset=0¦BottomOffset=0¦Orientation=2¦PaperLength=4200¦PaperWidth=2970¦Scale=100¦PaperSource=7¦PrintQuality=600¦MediaType=1¦DitherType=10¦PaperKind=A4¦PrintScaleMode=1; Author: Daniel Alesanco; SheetNumber: 8; SheetTotal: 13
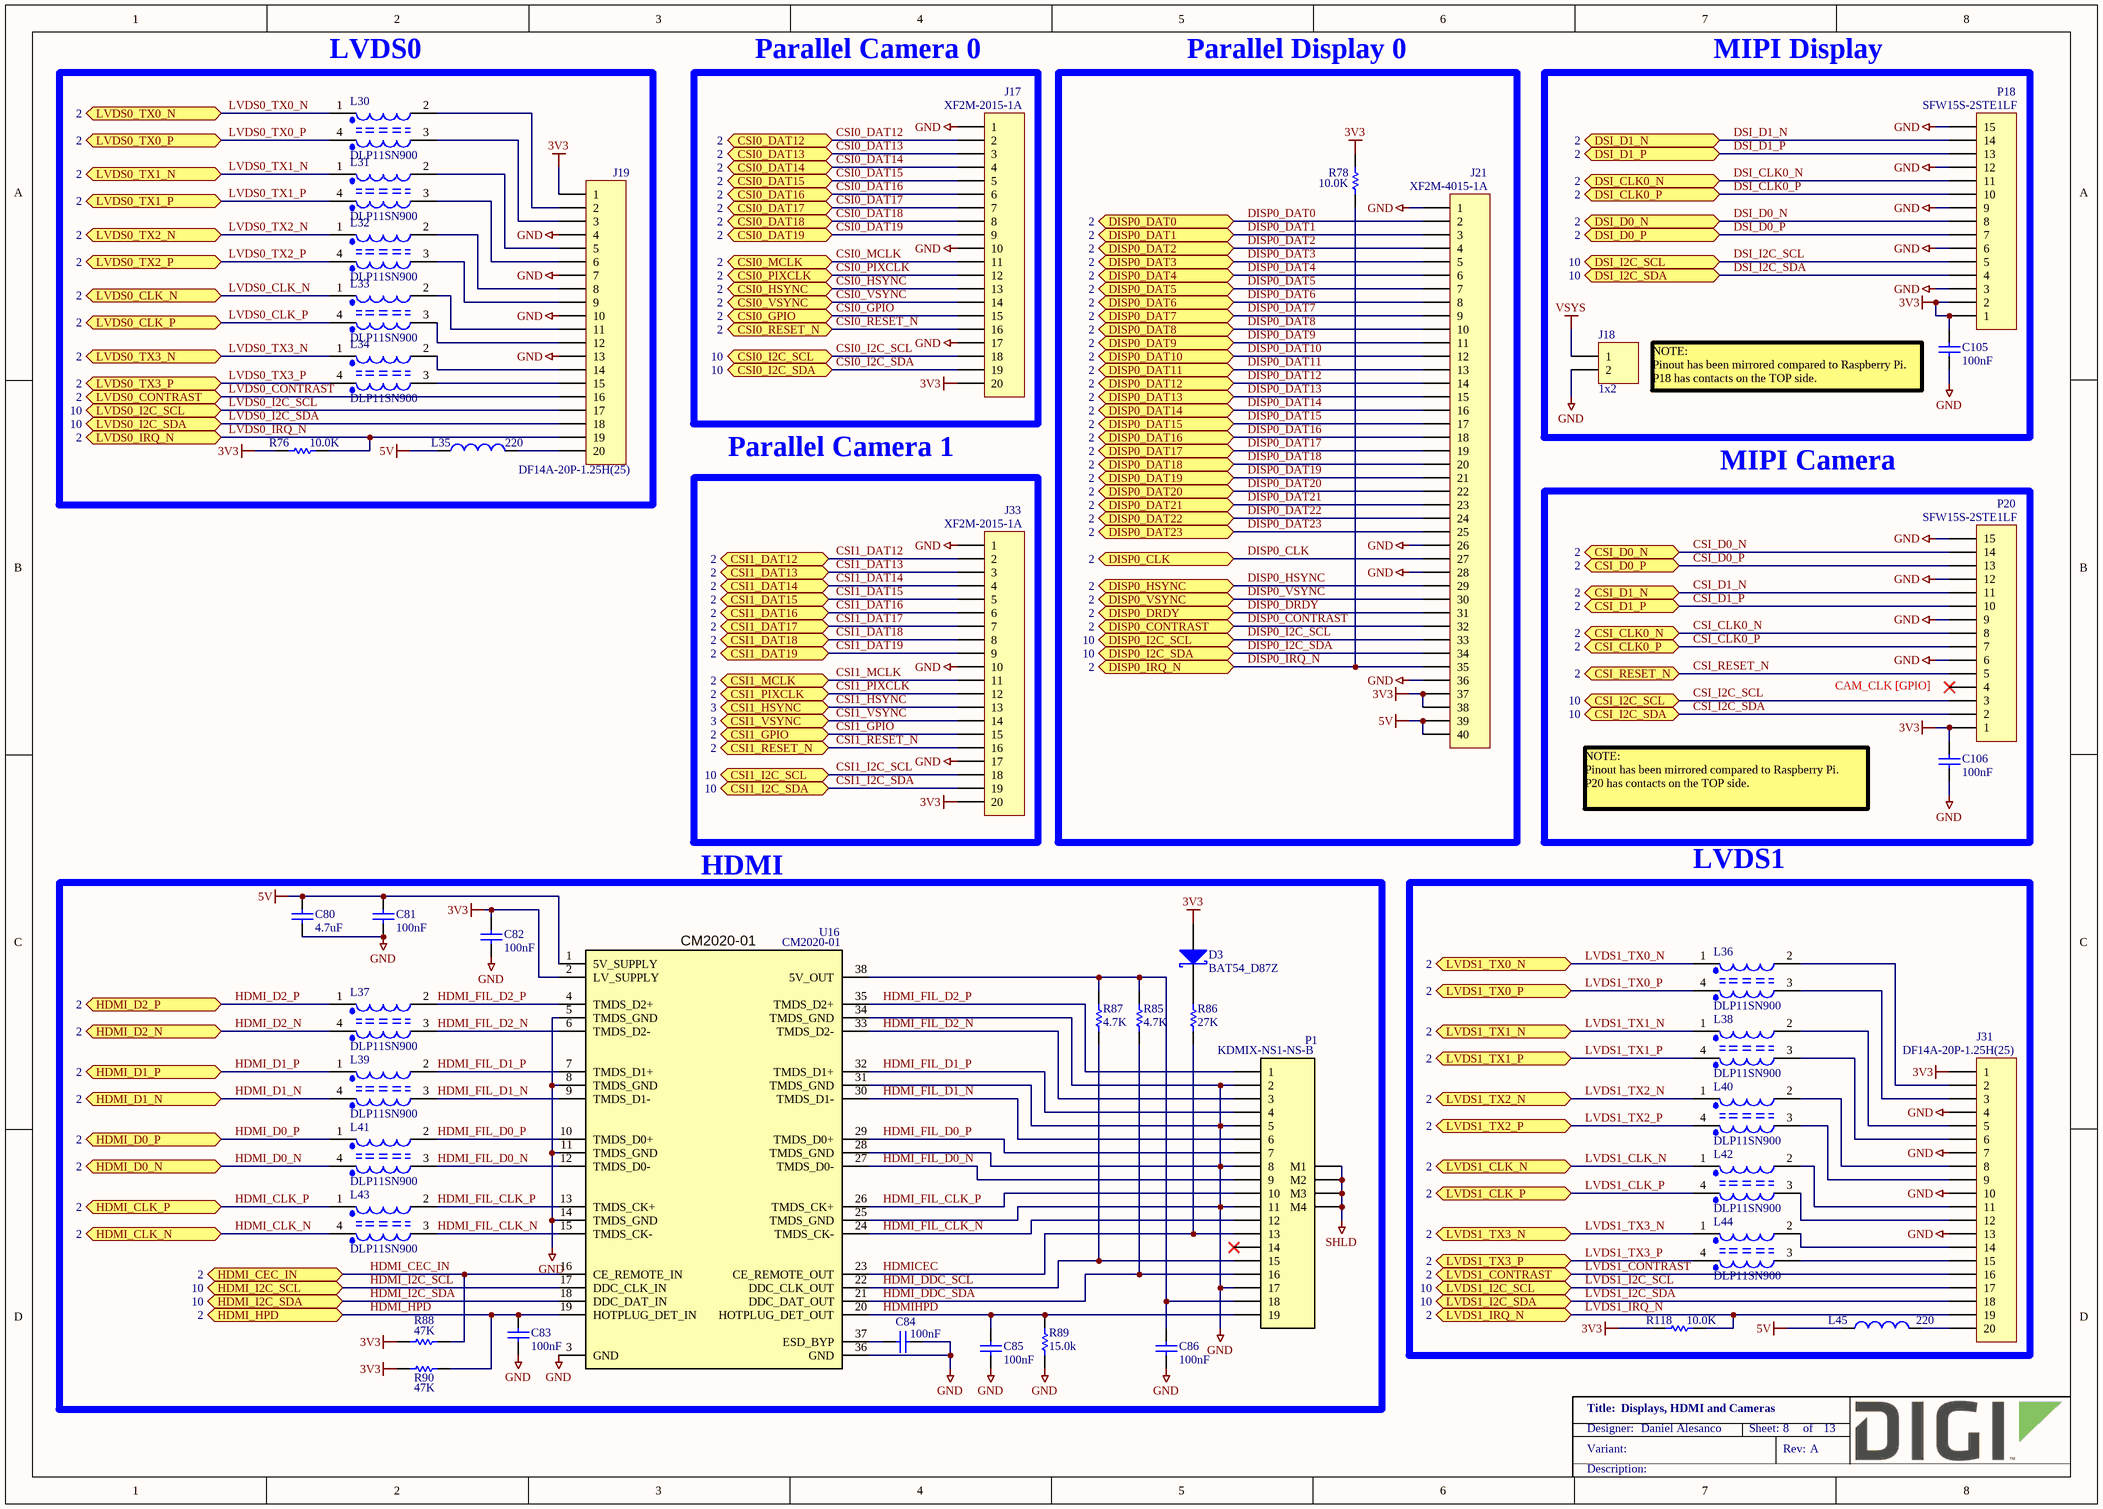
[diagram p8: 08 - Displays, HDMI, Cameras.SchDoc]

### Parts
C80  4.7uF  [CAPC2013X135N]
C81  100nF  [CAPC1005X55N]
C82  100nF  [CAPC1005X55N]
C83  100nF  [CAPC1005X55N]
C84  100nF  [CAPC1005X55N]
C85  100nF  [CAPC1005X55N]
C86  100nF  [CAPC1005X55N]
C105  100nF  [CAPC1005X55N]
C106  100nF  [CAPC1005X55N]
D3  BAT54_D87Z  [SOT95P240X110_AXK-3N]
J17  Manufacturer_Part_Number: XF2M-2015-1A  [omron_xf2m-2015-1a]  (hidden comment: 1x20P)
J18  1x2  [FCI_68002-102HLF]
J19  DF14A-20P-1.25H(25)  [HIROSE_DF14A-20P-1.25H]
J21  Manufacturer_Part_Number: XF2M-4015-1A  [OMRON_XF2M-4015-1A]  (hidden comment: 1x40)
J31  DF14A-20P-1.25H(25)  [HIROSE_DF14A-20P-1.25H]
J33  Manufacturer_Part_Number: XF2M-2015-1A  [omron_xf2m-2015-1a]  (hidden comment: 1x20P)
L30  DLP11SN900  [FIL_DLP11S]
L31  DLP11SN900  [FIL_DLP11S]
L32  DLP11SN900  [FIL_DLP11S]
L33  DLP11SN900  [FIL_DLP11S]
L34  DLP11SN900  [FIL_DLP11S]
L35  220  [INDC2013X110N]
L36  DLP11SN900  [FIL_DLP11S]
L37  DLP11SN900  [FIL_DLP11S]
L38  DLP11SN900  [FIL_DLP11S]
L39  DLP11SN900  [FIL_DLP11S]
L40  DLP11SN900  [FIL_DLP11S]
L41  DLP11SN900  [FIL_DLP11S]
L42  DLP11SN900  [FIL_DLP11S]
L43  DLP11SN900  [FIL_DLP11S]
L44  DLP11SN900  [FIL_DLP11S]
L45  220  [INDC2013X110N]
P1  KDMIX-NS1-NS-B  [KYCON_KDMIX]
P18  SFW15S-2STE1LF  [FCI_SFW15S-2STE1LF]
P20  SFW15S-2STE1LF  [FCI_SFW15S-2STE1LF]
R76  10.0K  [RESC1005X40N]
R78  10.0K  [RESC1005X40N]
R85  4.7K  [RESC1005X40N]
R86  27K  [RESC1005X40N]
R87  4.7K  [RESC1005X40N]
R88  47K  [RESC1005X40N]
R89  15.0k  [RESC1005X40N]
R90  47K  [RESC1005X40N]
R118  10.0K  [RESC1005X40N]
U16  CM2020-01  [SOP50P640X120-38N]

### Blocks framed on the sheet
LVDS0: J19 L30-L35 R76
Parallel Camera 0: J17
Parallel Display 0: J21 R78
MIPI Display: C105 J18 P18
Parallel Camera 1: J33
MIPI Camera: C106 P20
HDMI: C80-C86 D3 L37 L39 L41 L43 P1 R85-R90 U16
LVDS1: J31 L36 L38 L40 L42 L44 L45 R118

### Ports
CSI0_DAT12 (bidir, see 2), CSI0_DAT13 (bidir, see 2), CSI0_DAT14 (bidir, see 2), CSI0_DAT15 (bidir, see 2), CSI0_DAT16 (bidir, see 2), CSI0_DAT17 (bidir, see 2), CSI0_DAT18 (bidir, see 2), CSI0_DAT19 (bidir, see 2), CSI0_GPIO (bidir, see 2), CSI0_HSYNC (bidir, see 2), CSI0_I2C_SCL (bidir, see 10), CSI0_I2C_SDA (bidir, see 10), CSI0_MCLK (bidir, see 2), CSI0_PIXCLK (bidir, see 2), CSI0_RESET_N (bidir, see 2), CSI0_VSYNC (bidir, see 2), CSI1_DAT12 (bidir, see 2), CSI1_DAT13 (bidir, see 2), CSI1_DAT14 (bidir, see 2), CSI1_DAT15 (bidir, see 2), CSI1_DAT16 (bidir, see 2), CSI1_DAT17 (bidir, see 2), CSI1_DAT18 (bidir, see 2), CSI1_DAT19 (bidir, see 2), CSI1_GPIO (bidir, see 2), CSI1_HSYNC (bidir, see 3), CSI1_I2C_SCL (bidir, see 10), CSI1_I2C_SDA (bidir, see 10), CSI1_MCLK (bidir, see 2), CSI1_PIXCLK (bidir, see 2), CSI1_RESET_N (bidir, see 2), CSI1_VSYNC (bidir, see 3), CSI_CLK0_N (bidir, see 2), CSI_CLK0_P (bidir, see 2), CSI_D0_N (bidir, see 2), CSI_D0_P (bidir, see 2), CSI_D1_N (bidir, see 2), CSI_D1_P (bidir, see 2), CSI_I2C_SCL (bidir, see 10), CSI_I2C_SDA (bidir, see 10), CSI_RESET_N (bidir, see 2), DISP0_CLK (bidir, see 2), DISP0_CONTRAST (bidir, see 2), DISP0_DAT0 (bidir, see 2), DISP0_DAT1 (bidir, see 2), DISP0_DAT2 (bidir, see 2), DISP0_DAT3 (bidir, see 2), DISP0_DAT4 (bidir, see 2), DISP0_DAT5 (bidir, see 2), DISP0_DAT6 (bidir, see 2), DISP0_DAT7 (bidir, see 2), DISP0_DAT8 (bidir, see 2), DISP0_DAT9 (bidir, see 2), DISP0_DAT10 (bidir, see 2), DISP0_DAT11 (bidir, see 2), DISP0_DAT12 (bidir, see 2), DISP0_DAT13 (bidir, see 2), DISP0_DAT14 (bidir, see 2), DISP0_DAT15 (bidir, see 2), DISP0_DAT16 (bidir, see 2), DISP0_DAT17 (bidir, see 2), DISP0_DAT18 (bidir, see 2), DISP0_DAT19 (bidir, see 2), DISP0_DAT20 (bidir, see 2), DISP0_DAT21 (bidir, see 2), DISP0_DAT22 (bidir, see 2), DISP0_DAT23 (bidir, see 2), DISP0_DRDY (bidir, see 2), DISP0_HSYNC (bidir, see 2), DISP0_I2C_SCL (bidir, see 10), DISP0_I2C_SDA (bidir, see 10), DISP0_IRQ_N (bidir, see 2), DISP0_VSYNC (bidir, see 2), DSI_CLK0_N (bidir, see 2), DSI_CLK0_P (bidir, see 2), DSI_D0_N (bidir, see 2), DSI_D0_P (bidir, see 2), DSI_D1_N (bidir, see 2), DSI_D1_P (bidir, see 2), DSI_I2C_SCL (bidir, see 10), DSI_I2C_SDA (bidir, see 10), HDMI_CEC_IN (bidir, see 2), HDMI_CLK_N (bidir, see 2), HDMI_CLK_P (bidir, see 2), HDMI_D0_N (bidir, see 2), HDMI_D0_P (bidir, see 2), HDMI_D1_N (bidir, see 2), HDMI_D1_P (bidir, see 2), HDMI_D2_N (bidir, see 2), HDMI_D2_P (bidir, see 2), HDMI_HPD (bidir, see 2), HDMI_I2C_SCL (bidir, see 10), HDMI_I2C_SDA (bidir, see 10), LVDS0_CLK_N (bidir, see 2), LVDS0_CLK_P (bidir, see 2), LVDS0_CONTRAST (bidir, see 2), LVDS0_I2C_SCL (bidir, see 10), LVDS0_I2C_SDA (bidir, see 10), LVDS0_IRQ_N (bidir, see 2), LVDS0_TX0_N (bidir, see 2), LVDS0_TX0_P (bidir, see 2), LVDS0_TX1_N (bidir, see 2), LVDS0_TX1_P (bidir, see 2), LVDS0_TX2_N (bidir, see 2), LVDS0_TX2_P (bidir, see 2), LVDS0_TX3_N (bidir, see 2), LVDS0_TX3_P (bidir, see 2), LVDS1_CLK_N (bidir, see 2), LVDS1_CLK_P (bidir, see 2), LVDS1_CONTRAST (bidir, see 2), LVDS1_I2C_SCL (bidir, see 10), LVDS1_I2C_SDA (bidir, see 10), LVDS1_IRQ_N (bidir, see 2), LVDS1_TX0_N (bidir, see 2), LVDS1_TX0_P (bidir, see 2), LVDS1_TX1_N (bidir, see 2), LVDS1_TX1_P (bidir, see 2), LVDS1_TX2_N (bidir, see 2), LVDS1_TX2_P (bidir, see 2), LVDS1_TX3_N (bidir, see 2), LVDS1_TX3_P (bidir, see 2)

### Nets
3V3: C82.2 C105.2 C106.2 D3.A J17.20 J19.1 J21.37 J21.38 J31.1 J33.20 P18.1 P18.2 P20.1 R76.1 R78.1 R88.1 R90.1 R118.1 U16.2(LV_SUPPLY)
5V: C80.2 C81.2 J21.39 J21.40 L35.1 L45.1 U16.1(5V_SUPPLY)
GND: C80.1 C81.1 C82.1 C83.1 C84.1 C85.1 C86.1 C105.1 C106.1 J17.1 J17.10 J17.17 J18.2 J19.4 J19.7 J19.10 J19.13 J21.1 J21.26 J21.28 J21.36 J31.4 J31.7 J31.10 J31.13 J33.1 J33.10 J33.17 P1.2 P1.5 P1.8 P1.11 P1.17 P18.3 P18.6 P18.9 P18.12 P18.15 P20.6 P20.9 P20.12 P20.15 R89.1 U16.3(GND) U16.5(TMDS_GND) U16.8(TMDS_GND) U16.11(TMDS_GND) U16.14(TMDS_GND) U16.25(TMDS_GND) U16.28(TMDS_GND) U16.31(TMDS_GND) U16.34(TMDS_GND) U16.36(GND)
SHLD: P1.M1 P1.M2 P1.M3 P1.M4
VSYS: J18.1
CSI0_DAT12: J17.2 ; port CSI0_DAT12
CSI0_DAT13: J17.3 ; port CSI0_DAT13
CSI0_DAT14: J17.4 ; port CSI0_DAT14
CSI0_DAT15: J17.5 ; port CSI0_DAT15
CSI0_DAT16: J17.6 ; port CSI0_DAT16
CSI0_DAT17: J17.7 ; port CSI0_DAT17
CSI0_DAT18: J17.8 ; port CSI0_DAT18
CSI0_DAT19: J17.9 ; port CSI0_DAT19
CSI0_GPIO: J17.15 ; port CSI0_GPIO
CSI0_HSYNC: J17.13 ; port CSI0_HSYNC
CSI0_I2C_SCL: J17.18 ; port CSI0_I2C_SCL
CSI0_I2C_SDA: J17.19 ; port CSI0_I2C_SDA
CSI0_MCLK: J17.11 ; port CSI0_MCLK
CSI0_PIXCLK: J17.12 ; port CSI0_PIXCLK
CSI0_RESET_N: J17.16 ; port CSI0_RESET_N
CSI0_VSYNC: J17.14 ; port CSI0_VSYNC
CSI1_DAT12: J33.2 ; port CSI1_DAT12
CSI1_DAT13: J33.3 ; port CSI1_DAT13
CSI1_DAT14: J33.4 ; port CSI1_DAT14
CSI1_DAT15: J33.5 ; port CSI1_DAT15
CSI1_DAT16: J33.6 ; port CSI1_DAT16
CSI1_DAT17: J33.7 ; port CSI1_DAT17
CSI1_DAT18: J33.8 ; port CSI1_DAT18
CSI1_DAT19: J33.9 ; port CSI1_DAT19
CSI1_GPIO: J33.15 ; port CSI1_GPIO
CSI1_HSYNC: J33.13 ; port CSI1_HSYNC
CSI1_I2C_SCL: J33.18 ; port CSI1_I2C_SCL
CSI1_I2C_SDA: J33.19 ; port CSI1_I2C_SDA
CSI1_MCLK: J33.11 ; port CSI1_MCLK
CSI1_PIXCLK: J33.12 ; port CSI1_PIXCLK
CSI1_RESET_N: J33.16 ; port CSI1_RESET_N
CSI1_VSYNC: J33.14 ; port CSI1_VSYNC
CSI_CLK0_N: P20.8 ; port CSI_CLK0_N
CSI_CLK0_P: P20.7 ; port CSI_CLK0_P
CSI_D0_N: P20.14 ; port CSI_D0_N
CSI_D0_P: P20.13 ; port CSI_D0_P
CSI_D1_N: P20.11 ; port CSI_D1_N
CSI_D1_P: P20.10 ; port CSI_D1_P
CSI_I2C_SCL: P20.3 ; port CSI_I2C_SCL
CSI_I2C_SDA: P20.2 ; port CSI_I2C_SDA
CSI_RESET_N: P20.5 ; port CSI_RESET_N
DISP0_CLK: J21.27 ; port DISP0_CLK
DISP0_CONTRAST: J21.32 ; port DISP0_CONTRAST
DISP0_DAT0: J21.2 ; port DISP0_DAT0
DISP0_DAT1: J21.3 ; port DISP0_DAT1
DISP0_DAT2: J21.4 ; port DISP0_DAT2
DISP0_DAT3: J21.5 ; port DISP0_DAT3
DISP0_DAT4: J21.6 ; port DISP0_DAT4
DISP0_DAT5: J21.7 ; port DISP0_DAT5
DISP0_DAT6: J21.8 ; port DISP0_DAT6
DISP0_DAT7: J21.9 ; port DISP0_DAT7
DISP0_DAT8: J21.10 ; port DISP0_DAT8
DISP0_DAT9: J21.11 ; port DISP0_DAT9
DISP0_DAT10: J21.12 ; port DISP0_DAT10
DISP0_DAT11: J21.13 ; port DISP0_DAT11
DISP0_DAT12: J21.14 ; port DISP0_DAT12
DISP0_DAT13: J21.15 ; port DISP0_DAT13
DISP0_DAT14: J21.16 ; port DISP0_DAT14
DISP0_DAT15: J21.17 ; port DISP0_DAT15
DISP0_DAT16: J21.18 ; port DISP0_DAT16
DISP0_DAT17: J21.19 ; port DISP0_DAT17
DISP0_DAT18: J21.20 ; port DISP0_DAT18
DISP0_DAT19: J21.21 ; port DISP0_DAT19
DISP0_DAT20: J21.22 ; port DISP0_DAT20
DISP0_DAT21: J21.23 ; port DISP0_DAT21
DISP0_DAT22: J21.24 ; port DISP0_DAT22
DISP0_DAT23: J21.25 ; port DISP0_DAT23
DISP0_DRDY: J21.31 ; port DISP0_DRDY
DISP0_HSYNC: J21.29 ; port DISP0_HSYNC
DISP0_I2C_SCL: J21.33 ; port DISP0_I2C_SCL
DISP0_I2C_SDA: J21.34 ; port DISP0_I2C_SDA
DISP0_IRQ_N: J21.35 R78.2 ; port DISP0_IRQ_N
DISP0_VSYNC: J21.30 ; port DISP0_VSYNC
DSI_CLK0_N: P18.11 ; port DSI_CLK0_N
DSI_CLK0_P: P18.10 ; port DSI_CLK0_P
DSI_D0_N: P18.8 ; port DSI_D0_N
DSI_D0_P: P18.7 ; port DSI_D0_P
DSI_D1_N: P18.14 ; port DSI_D1_N
DSI_D1_P: P18.13 ; port DSI_D1_P
DSI_I2C_SCL: P18.5 ; port DSI_I2C_SCL
DSI_I2C_SDA: P18.4 ; port DSI_I2C_SDA
HDMI_CEC_IN: R88.2 U16.16(CE_REMOTE_IN) ; port HDMI_CEC_IN
HDMI_CLK_N: L43.4 ; port HDMI_CLK_N
HDMI_CLK_P: L43.1 ; port HDMI_CLK_P
HDMI_D0_N: L41.4 ; port HDMI_D0_N
HDMI_D0_P: L41.1 ; port HDMI_D0_P
HDMI_D1_N: L39.4 ; port HDMI_D1_N
HDMI_D1_P: L39.1 ; port HDMI_D1_P
HDMI_D2_N: L37.4 ; port HDMI_D2_N
HDMI_D2_P: L37.1 ; port HDMI_D2_P
HDMI_DDC_SCL: P1.15 R87.1 U16.22(DDC_CLK_OUT)
HDMI_DDC_SDA: P1.16 R85.1 U16.21(DDC_DAT_OUT)
HDMI_FIL_CLK_N: L43.3 P1.12 U16.15(TMDS_CK-) U16.24(TMDS_CK-)
HDMI_FIL_CLK_P: L43.2 P1.10 U16.13(TMDS_CK+) U16.26(TMDS_CK+)
HDMI_FIL_D0_N: L41.3 P1.9 U16.12(TMDS_D0-) U16.27(TMDS_D0-)
HDMI_FIL_D0_P: L41.2 P1.7 U16.10(TMDS_D0+) U16.29(TMDS_D0+)
HDMI_FIL_D1_N: L39.3 P1.6 U16.9(TMDS_D1-) U16.30(TMDS_D1-)
HDMI_FIL_D1_P: L39.2 P1.4 U16.7(TMDS_D1+) U16.32(TMDS_D1+)
HDMI_FIL_D2_N: L37.3 P1.3 U16.6(TMDS_D2-) U16.33(TMDS_D2-)
HDMI_FIL_D2_P: L37.2 P1.1 U16.4(TMDS_D2+) U16.35(TMDS_D2+)
HDMI_HPD: C83.2 R90.2 U16.19(HOTPLUG_DET_IN) ; port HDMI_HPD
HDMI_I2C_SCL: U16.17(DDC_CLK_IN) ; port HDMI_I2C_SCL
HDMI_I2C_SDA: U16.18(DDC_DAT_IN) ; port HDMI_I2C_SDA
HDMICEC: P1.13 R86.2 U16.23(CE_REMOTE_OUT)
HDMIHPD: C85.2 P1.19 R89.2 U16.20(HOTPLUG_DET_OUT)
LVDS0_CLK_N: L33.1 ; port LVDS0_CLK_N
LVDS0_CLK_P: L33.4 ; port LVDS0_CLK_P
LVDS0_CONTRAST: J19.16 ; port LVDS0_CONTRAST
LVDS0_I2C_SCL: J19.17 ; port LVDS0_I2C_SCL
LVDS0_I2C_SDA: J19.18 ; port LVDS0_I2C_SDA
LVDS0_IRQ_N: J19.19 R76.2 ; port LVDS0_IRQ_N
LVDS0_TX0_N: L30.1 ; port LVDS0_TX0_N
LVDS0_TX0_P: L30.4 ; port LVDS0_TX0_P
LVDS0_TX1_N: L31.1 ; port LVDS0_TX1_N
LVDS0_TX1_P: L31.4 ; port LVDS0_TX1_P
LVDS0_TX2_N: L32.1 ; port LVDS0_TX2_N
LVDS0_TX2_P: L32.4 ; port LVDS0_TX2_P
LVDS0_TX3_N: L34.1 ; port LVDS0_TX3_N
LVDS0_TX3_P: L34.4 ; port LVDS0_TX3_P
LVDS1_CLK_N: L42.1 ; port LVDS1_CLK_N
LVDS1_CLK_P: L42.4 ; port LVDS1_CLK_P
LVDS1_CONTRAST: J31.16 ; port LVDS1_CONTRAST
LVDS1_I2C_SCL: J31.17 ; port LVDS1_I2C_SCL
LVDS1_I2C_SDA: J31.18 ; port LVDS1_I2C_SDA
LVDS1_IRQ_N: J31.19 R118.2 ; port LVDS1_IRQ_N
LVDS1_TX0_N: L36.1 ; port LVDS1_TX0_N
LVDS1_TX0_P: L36.4 ; port LVDS1_TX0_P
LVDS1_TX1_N: L38.1 ; port LVDS1_TX1_N
LVDS1_TX1_P: L38.4 ; port LVDS1_TX1_P
LVDS1_TX2_N: L40.1 ; port LVDS1_TX2_N
LVDS1_TX2_P: L40.4 ; port LVDS1_TX2_P
LVDS1_TX3_N: L44.1 ; port LVDS1_TX3_N
LVDS1_TX3_P: L44.4 ; port LVDS1_TX3_P
NetC84_2: C84.2 U16.37(ESD_BYP)
NetC86_2: C86.2 P1.18 R85.2 R87.2 U16.38(5V_OUT)
NetD3_K: D3.K R86.1
NetJ19_2: J19.2 L30.2
NetJ19_3: J19.3 L30.3
NetJ19_5: J19.5 L31.2
NetJ19_6: J19.6 L31.3
NetJ19_8: J19.8 L32.2
NetJ19_9: J19.9 L32.3
NetJ19_11: J19.11 L33.2
NetJ19_12: J19.12 L33.3
NetJ19_14: J19.14 L34.2
NetJ19_15: J19.15 L34.3
NetJ19_20: J19.20 L35.2
NetJ31_2: J31.2 L36.2
NetJ31_3: J31.3 L36.3
NetJ31_5: J31.5 L38.2
NetJ31_6: J31.6 L38.3
NetJ31_8: J31.8 L40.2
NetJ31_9: J31.9 L40.3
NetJ31_11: J31.11 L42.2
NetJ31_12: J31.12 L42.3
NetJ31_14: J31.14 L44.2
NetJ31_15: J31.15 L44.3
NetJ31_20: J31.20 L45.2

Not connected (* = marked no-connect by the designer): P1 14*; P20 4*

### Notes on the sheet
- (near C105) NOTE:
  Pinout has been mirrored compared to Raspberry Pi.
  P18 has contacts on the TOP side.
- CAM_CLK [GPIO]
- NOTE:
  Pinout has been mirrored compared to Raspberry Pi.
  P20 has contacts on the TOP side.

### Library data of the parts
C80 = 1000500: CAP CER 4.7UF 25V 10% X5R 0805; Part_Type: Capacitor; Manufacturer: Murata; Manufacturer_Part_Number: GRM21BR61E475KA12L; Component_Life_Cycle_State: Reviewed; Area: 4.24; Project: SDR Prototype RF Board; Digi_PN: 14050307
C81-C86 C105 C106 = 1000006: as C18-C27 on sheet 05 - JTAG, SWD, Console, UART
D3 = 1001169: DIODE SCHOTTKY 30V 0.2A SOT23-3; Part_Type: IC; Manufacturer: Fairchild Semiconductor; Digi_PN: 17050507; Component_Life_Cycle_State: Reviewed; Area: 8; Project: CCWMX6_SBC board
J17 J33 = 1001145: CONN FPC 20POS 0.5MM PITCH SMD; Part_Type: Connector; Manufacturer: Omron; Digi_PN: 18000675; Component_Life_Cycle_State: Reviewed; Area: 69.09; Project: CCWMX6_SBC board
J18 = 1001128: CONN HEADER 2POS .100" SGL GOLD; Part_Type: Connector; Manufacturer: Samtec; Manufacturer_Part_Number: TSW-102-07-G-S; Digi_PN: 00120002; Component_Life_Cycle_State: Reviewed; Area: 12.9032; Project: CCWMX6_SBC board
J19 J31 = 1001132: CONN HEADER 20POS 1.25MM R/A SMD; Part_Type: Connector; Manufacturer: Hirose; Digi_PN: 18050231; Component_Life_Cycle_State: Reviewed; Area: 206.34; Project: CCWMX6_SBC board
J21 = 1001144: CONN FPC 40POS 0.5MM PITCH SMD; Part_Type: Connector; Manufacturer: Omron; Digi_PN: 18000676; Component_Life_Cycle_State: Reviewed; Area: 117.5; Project: CCWMX6_SBC board
L30-L34 L36-L44 = 1001014: CHOKE COIL COMMON MODE 150MA SMD; Part_Type: Inductor; Manufacturer: Murata; Manufacturer_Part_Number: DLP11SN900HL2L; Component_Life_Cycle_State: Reviewed; Area: 3.94; Project: ResMed RF Test Interface Board; Digi_PN: 21000531
L35 L45 = 1001174: as L6 on sheet 07 - USB OTG, USB HUB, USB Host
P1 = 1001123: HDMI RECEPTACLE, SMT; Part_Type: Connector; Manufacturer: KYCON; Digi_PN: 18000451; Component_Life_Cycle_State: Reviewed; Area: 174; Project: CCWMX6_SBC board
P18 P20 = 1001866: CONN FFC FPC VERT 15POS 1MM SMD; Part_Type: Connector; Manufacturer: FCI; Component_Life_Cycle_State: Reviewed; Area: 128.76; Project: CCiMX6 SBC MFG TEST BOARD; Digi_PN: 18000730
R76 R78 R118 = 1000537: as R36 on sheet 05 - JTAG, SWD, Console, UART
R85 R87 = 1000038: as R37 on sheet 05 - JTAG, SWD, Console, UART
R86 = 1001153: RES 27.0K OHM 1/16W 1% 0402 SMD; Part_Type: Resistor; Manufacturer: Yageo; Manufacturer_Part_Number: RC0402FR-0727KL; Digi_PN: 13050609; Component_Life_Cycle_State: Reviewed; Area: 0.95; Project: CCWMX6_SBC board
R88 R90 = 1001155: as R26 on sheet 06 - Gigabit Ethernet
R89 = 1000174: RES 15.0K OHM 1/10W 1% 0402 SMD; Part_Type: Resistor; Manufacturer: Panasonic - ECG; Manufacturer_Part_Number: ERJ-2RKF1502X; Component_Life_Cycle_State: CAD Reviewed; Area: 0.95; Project: KITT; Power_WV_SRF: 10; Digi_PN: 13050446
U16 = 1001125: IC HDMI XMITTER PORT P/I 38TSSOP; Manufacturer: On Semiconductor; Digi_PN: 16051861; Component_Life_Cycle_State: Reviewed; Area: 43; Project: CCWMX6_SBC board

## Sheet 09 - Audio.SchDoc: Audio
size A3; PageSetup: Record=PageOptions¦CenterHorizontal=True¦CenterVertical=True¦PrintScale=0.70¦XCorrection=1.00¦YCorrection=1.00¦PrintKind=0¦BorderSize=5000000¦LeftOffset=0¦BottomOffset=0¦Orientation=2¦PaperLength=4200¦PaperWidth=2970¦Scale=100¦PaperSource=7¦PrintQuality=600¦MediaType=1¦DitherType=10¦PaperKind=A4¦PrintScaleMode=1; Author: Daniel Alesanco; SheetNumber: 9; SheetTotal: 13
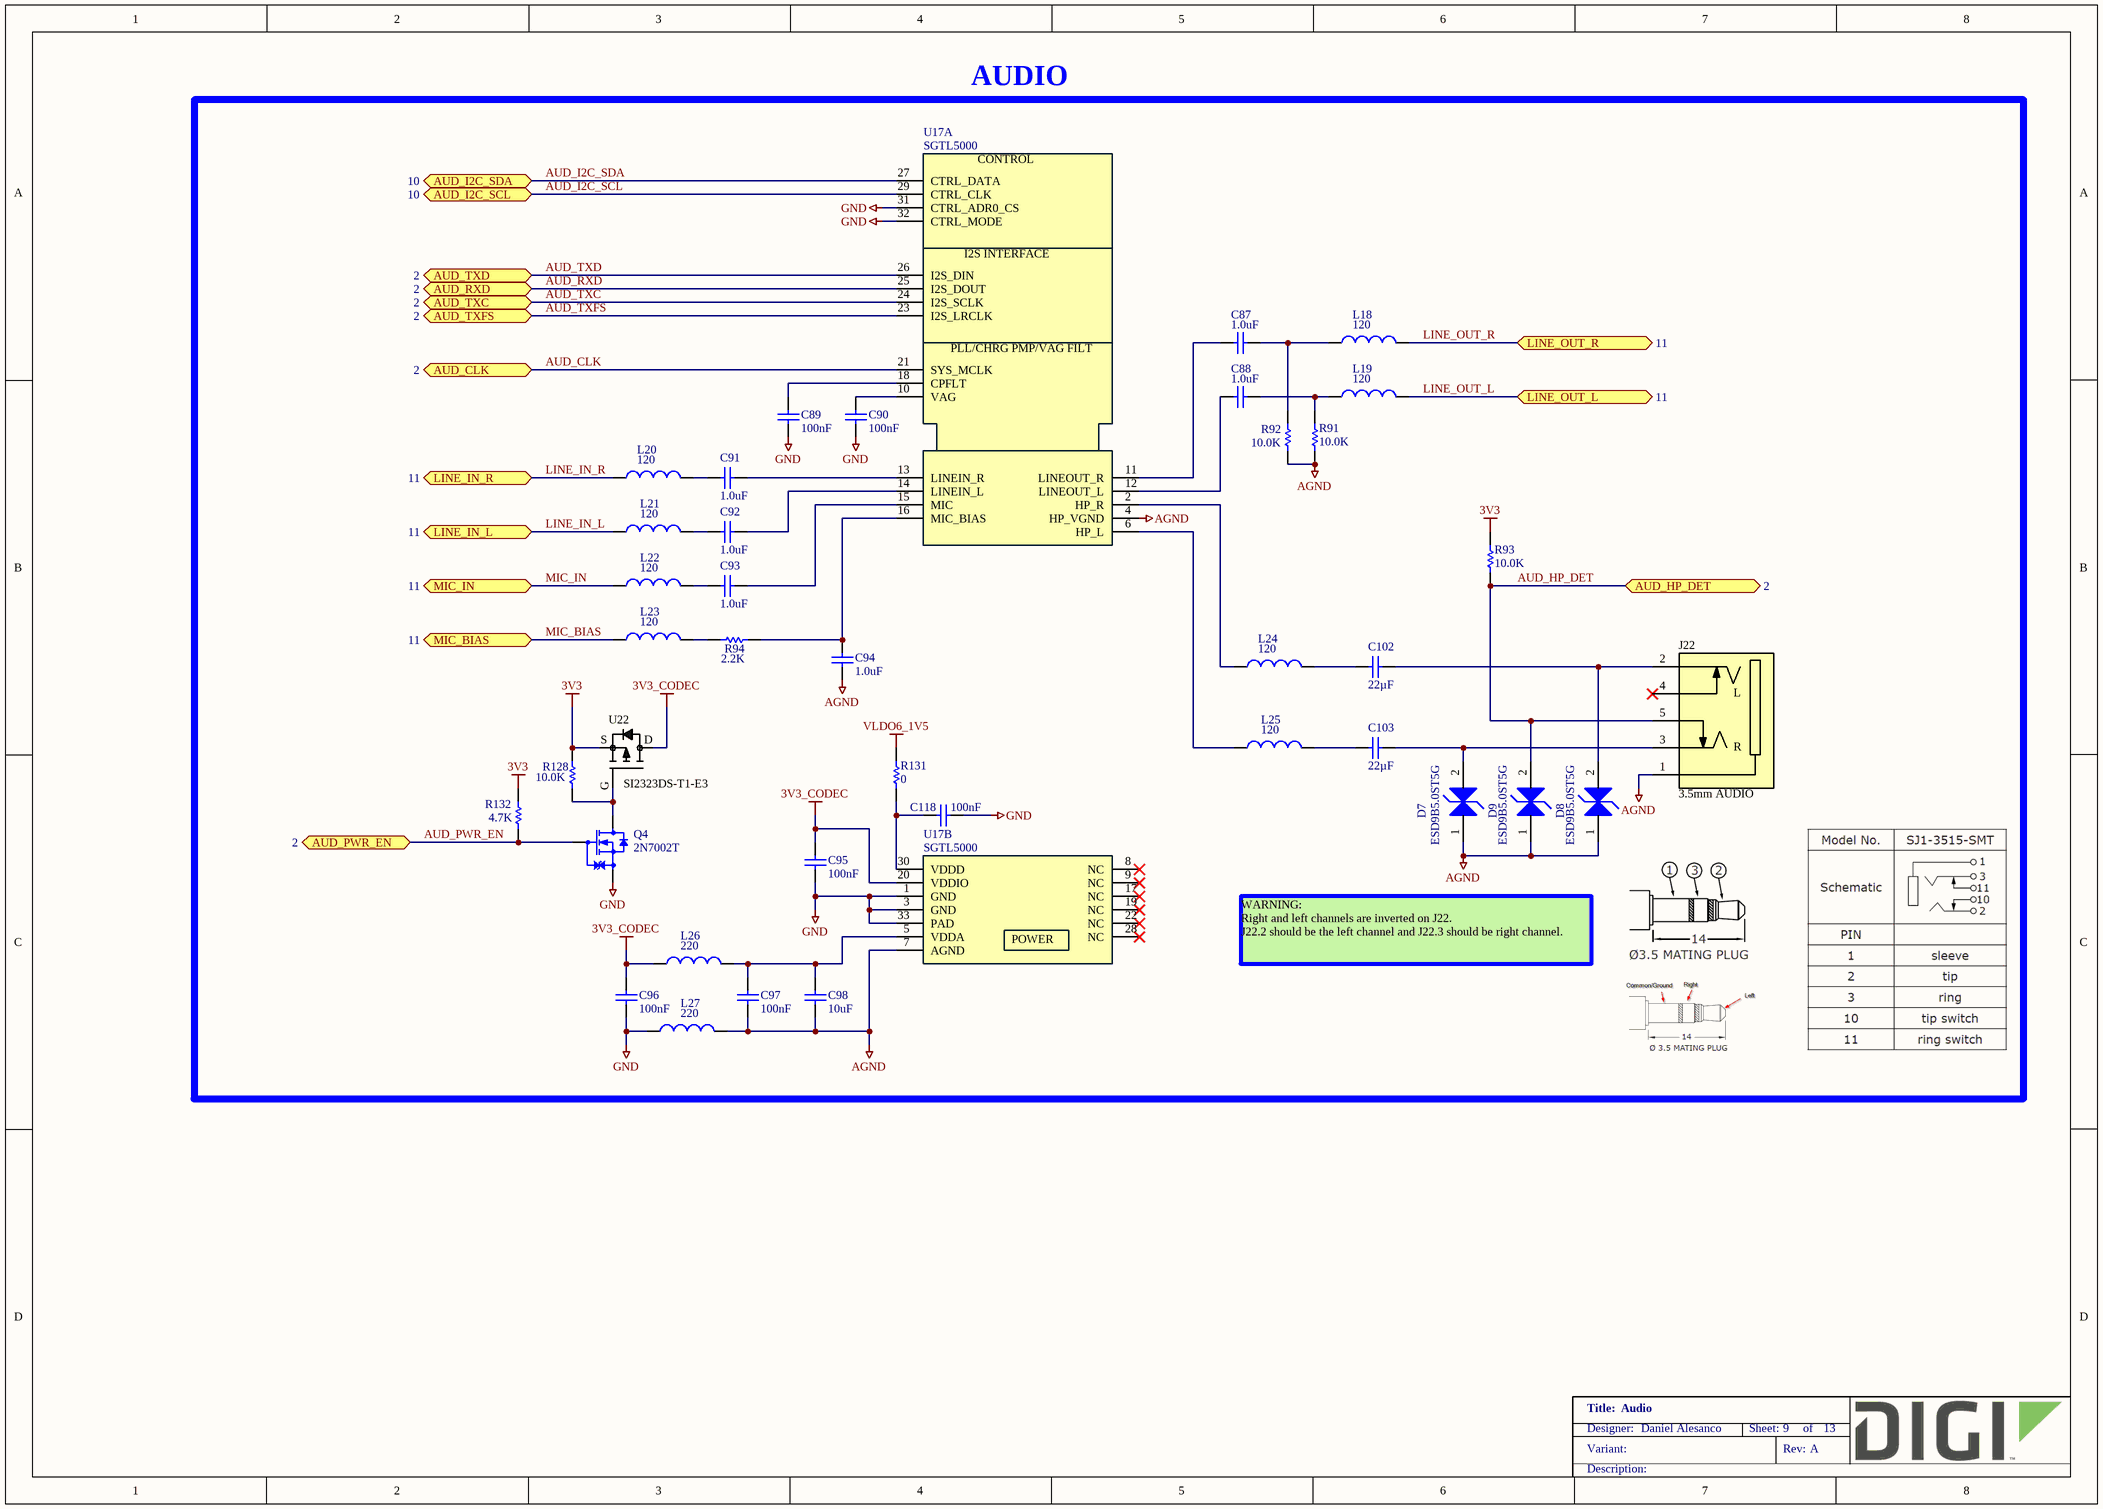
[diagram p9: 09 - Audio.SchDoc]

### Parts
C87  1.0uF  [CAPC1005X55N]
C88  1.0uF  [CAPC1005X55N]
C89  100nF  [CAPC1005X55N]
C90  100nF  [CAPC1005X55N]
C91  1.0uF  [CAPC1005X55N]
C92  1.0uF  [CAPC1005X55N]
C93  1.0uF  [CAPC1005X55N]
C94  1.0uF  [CAPC1005X55N]
C95  100nF  [CAPC1005X55N]
C96  100nF  [CAPC1005X55N]
C97  100nF  [CAPC1005X55N]
C98  10uF  [CAPC1005X55N]
C102  22µF  [CAPC1608X90N]
C103  22µF  [CAPC1608X90N]
C118  100nF  [CAPC1005X55N]
D7  ESD9B5.0ST5G  [SODFL1006X43N12]
D8  ESD9B5.0ST5G  [SODFL1006X43N12]
D9  ESD9B5.0ST5G  [SODFL1006X43N12]
J22  3.5mm AUDIO  [CUI_SJ1-3515-SMT]
L18  120  [INDC1005X60N]
L19  120  [INDC1005X60N]
L20  120  [INDC1005X60N]
L21  120  [INDC1005X60N]
L22  120  [INDC1005X60N]
L23  120  [INDC1005X60N]
L24  120  [INDC1005X60N]
L25  120  [INDC1005X60N]
L26  220  [INDC2013X110N]
L27  220  [INDC2013X110N]
Q4  2N7002T  [SOTFL50P160X80_GSD-3N]
R91  10.0K  [RESC1005X40N]
R92  10.0K  [RESC1005X40N]
R93  10.0K  [RESC1005X40N]
R94  2.2K  [RESC1005X40N]
R128  10.0K  [RESC1005X40N]
R131  0  [RESC1005X40N]
R132  4.7K  [RESC1005X40N]
U17  SGTL5000  [QFN50P500X500X100-33CN]  (parts A,B of 2)
U22  SI2323DS-T1-E3  [SOT95P240X110_GSD-3N]

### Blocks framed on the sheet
AUDIO: C87-C98 C102 C103 C118 D7-D9 J22 L18-L27 Q4 R91-R94 R128 R131 R132 U17 U22

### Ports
AUD_CLK (bidir, see 2), AUD_HP_DET (bidir, see 2), AUD_I2C_SCL (bidir, see 10), AUD_I2C_SDA (bidir, see 10), AUD_PWR_EN (bidir, see 2), AUD_RXD (bidir, see 2), AUD_TXC (bidir, see 2), AUD_TXD (bidir, see 2), AUD_TXFS (bidir, see 2), LINE_IN_L (bidir, see 11), LINE_IN_R (bidir, see 11), LINE_OUT_L (bidir, see 11), LINE_OUT_R (bidir, see 11), MIC_BIAS (bidir, see 11), MIC_IN (bidir, see 11)

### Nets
3V3: R93.2 R128.1 R132.2 U22.S
3V3_CODEC: C95.2 C96.2 L26.1 U17.20(VDDIO) U22.D
AGND: C94.1 C97.1 C98.1 D7.1 D8.1 D9.1 J22.1 L27.2 R91.1 R92.1 U17.4(HP_VGND) U17.7(AGND)
GND: C89.1 C90.1 C95.1 C96.1 C118.1 L27.1 Q4.S U17.1(GND) U17.3(GND) U17.31(CTRL_ADR0_CS) U17.32(CTRL_MODE) U17.33(PAD)
VLDO6_1V5: R131.2
AUD_CLK: U17.21(SYS_MCLK) ; port AUD_CLK
AUD_HP_DET: D9.2 J22.5 R93.1 ; port AUD_HP_DET
AUD_I2C_SCL: U17.29(CTRL_CLK) ; port AUD_I2C_SCL
AUD_I2C_SDA: U17.27(CTRL_DATA) ; port AUD_I2C_SDA
AUD_PWR_EN: Q4.G R132.1 ; port AUD_PWR_EN
AUD_RXD: U17.25(I2S_DOUT) ; port AUD_RXD
AUD_TXC: U17.24(I2S_SCLK) ; port AUD_TXC
AUD_TXD: U17.26(I2S_DIN) ; port AUD_TXD
AUD_TXFS: U17.23(I2S_LRCLK) ; port AUD_TXFS
LINE_IN_L: L21.1 ; port LINE_IN_L
LINE_IN_R: L20.1 ; port LINE_IN_R
LINE_OUT_L: L19.2 ; port LINE_OUT_L
LINE_OUT_R: L18.2 ; port LINE_OUT_R
MIC_BIAS: L23.1 ; port MIC_BIAS
MIC_IN: L22.1 ; port MIC_IN
NetC87_1: C87.1 U17.11(LINEOUT_R)
NetC87_2: C87.2 L18.1 R92.2
NetC88_1: C88.1 U17.12(LINEOUT_L)
NetC88_2: C88.2 L19.1 R91.2
NetC89_2: C89.2 U17.18(CPFLT)
NetC90_2: C90.2 U17.10(VAG)
NetC91_1: C91.1 L20.2
NetC91_2: C91.2 U17.13(LINEIN_R)
NetC92_1: C92.1 L21.2
NetC92_2: C92.2 U17.14(LINEIN_L)
NetC93_1: C93.1 L22.2
NetC93_2: C93.2 U17.15(MIC)
NetC94_2: C94.2 R94.2 U17.16(MIC_BIAS)
NetC97_2: C97.2 C98.2 L26.2 U17.5(VDDA)
NetC102_1: C102.1 D8.2 J22.2
NetC102_2: C102.2 L24.2
NetC103_1: C103.1 D7.2 J22.3
NetC103_2: C103.2 L25.2
NetC118_2: C118.2 R131.1 U17.30(VDDD)
NetL23_2: L23.2 R94.1
NetL24_1: L24.1 U17.2(HP_R)
NetL25_1: L25.1 U17.6(HP_L)
NetQ4_D: Q4.D R128.2 U22.G

Not connected (* = marked no-connect by the designer): J22 4*; U17 8(NC)* 9(NC)* 17(NC)* 19(NC)* 22(NC)* 28(NC)*

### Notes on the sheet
- WARNING:
  Right and left channels are inverted on J22.
  J22.2 should be the left channel and J22.3 should be right channel.

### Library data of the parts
C87 C88 C91-C94 = 1001167: as C104 on sheet 06 - Gigabit Ethernet
C89 C90 C95-C97 C118 = 1000006: as C18-C27 on sheet 05 - JTAG, SWD, Console, UART
C98 = 1001168: as C42 on sheet 06 - Gigabit Ethernet
C102 C103 = 1000998: CAP CER 22UF 10V 20% X5R 0603; Part_Type: Capacitor; Manufacturer: Samsung; Manufacturer_Part_Number: CL10A226MP8NUNE; Manufacturer_Alt_1: TDK Corporation; Manufacturer_Alt_1_Part_Number: C1608X5R1A226M080AC; Digi_PN: 14050684; Component_Life_Cycle_State: Reviewed; Area: 2.27; Project: ConnectCore i.MX6 module; Tolerance: 20
D7-D9 = 1001264: as D10 on sheet 07 - USB OTG, USB HUB, USB Host
J22 = 1001133: CONN JACK STEREO 5POS 3.5MM SMD; Part_Type: Connector; Manufacturer: CUI Inc.; Manufacturer_Part_Number: SJ1-3515-SMT; Digi_PN: MA02822; Component_Life_Cycle_State: Reviewed; Area: 114; Project: CCWMX6_SBC board
L18-L25 = 1001175: as L2 on sheet 06 - Gigabit Ethernet
L26 L27 = 1001174: as L6 on sheet 07 - USB OTG, USB HUB, USB Host
Q4 = 1000715: as Q2 on sheet 07 - USB OTG, USB HUB, USB Host
R91-R93 R128 = 1000537: as R36 on sheet 05 - JTAG, SWD, Console, UART
R94 = 1001156: RES 2.20K OHM 1/16W 1% 0402 SMD; Part_Type: Resistor; Manufacturer: Yageo; Manufacturer_Part_Number: RC0402FR-072K2L; Digi_PN: 13050699; Component_Life_Cycle_State: Reviewed; Area: 0.95; Project: CCWMX6_SBC board; Note: 13051099 = Digi No. for GE WDNU
R131 = 1000076: as R149-R152 on sheet 05 - JTAG, SWD, Console, UART
R132 = 1000038: as R37 on sheet 05 - JTAG, SWD, Console, UART
U17 = 1001126: IC AUDIO CODEC STEREO 32-QFN; Manufacturer: Freescale Semiconductor; Digi_PN: 16051534; Component_Life_Cycle_State: Reviewed; Area: 25; Project: CCWMX6_SBC board
U22 = 1001163: as U15 on sheet 07 - USB OTG, USB HUB, USB Host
